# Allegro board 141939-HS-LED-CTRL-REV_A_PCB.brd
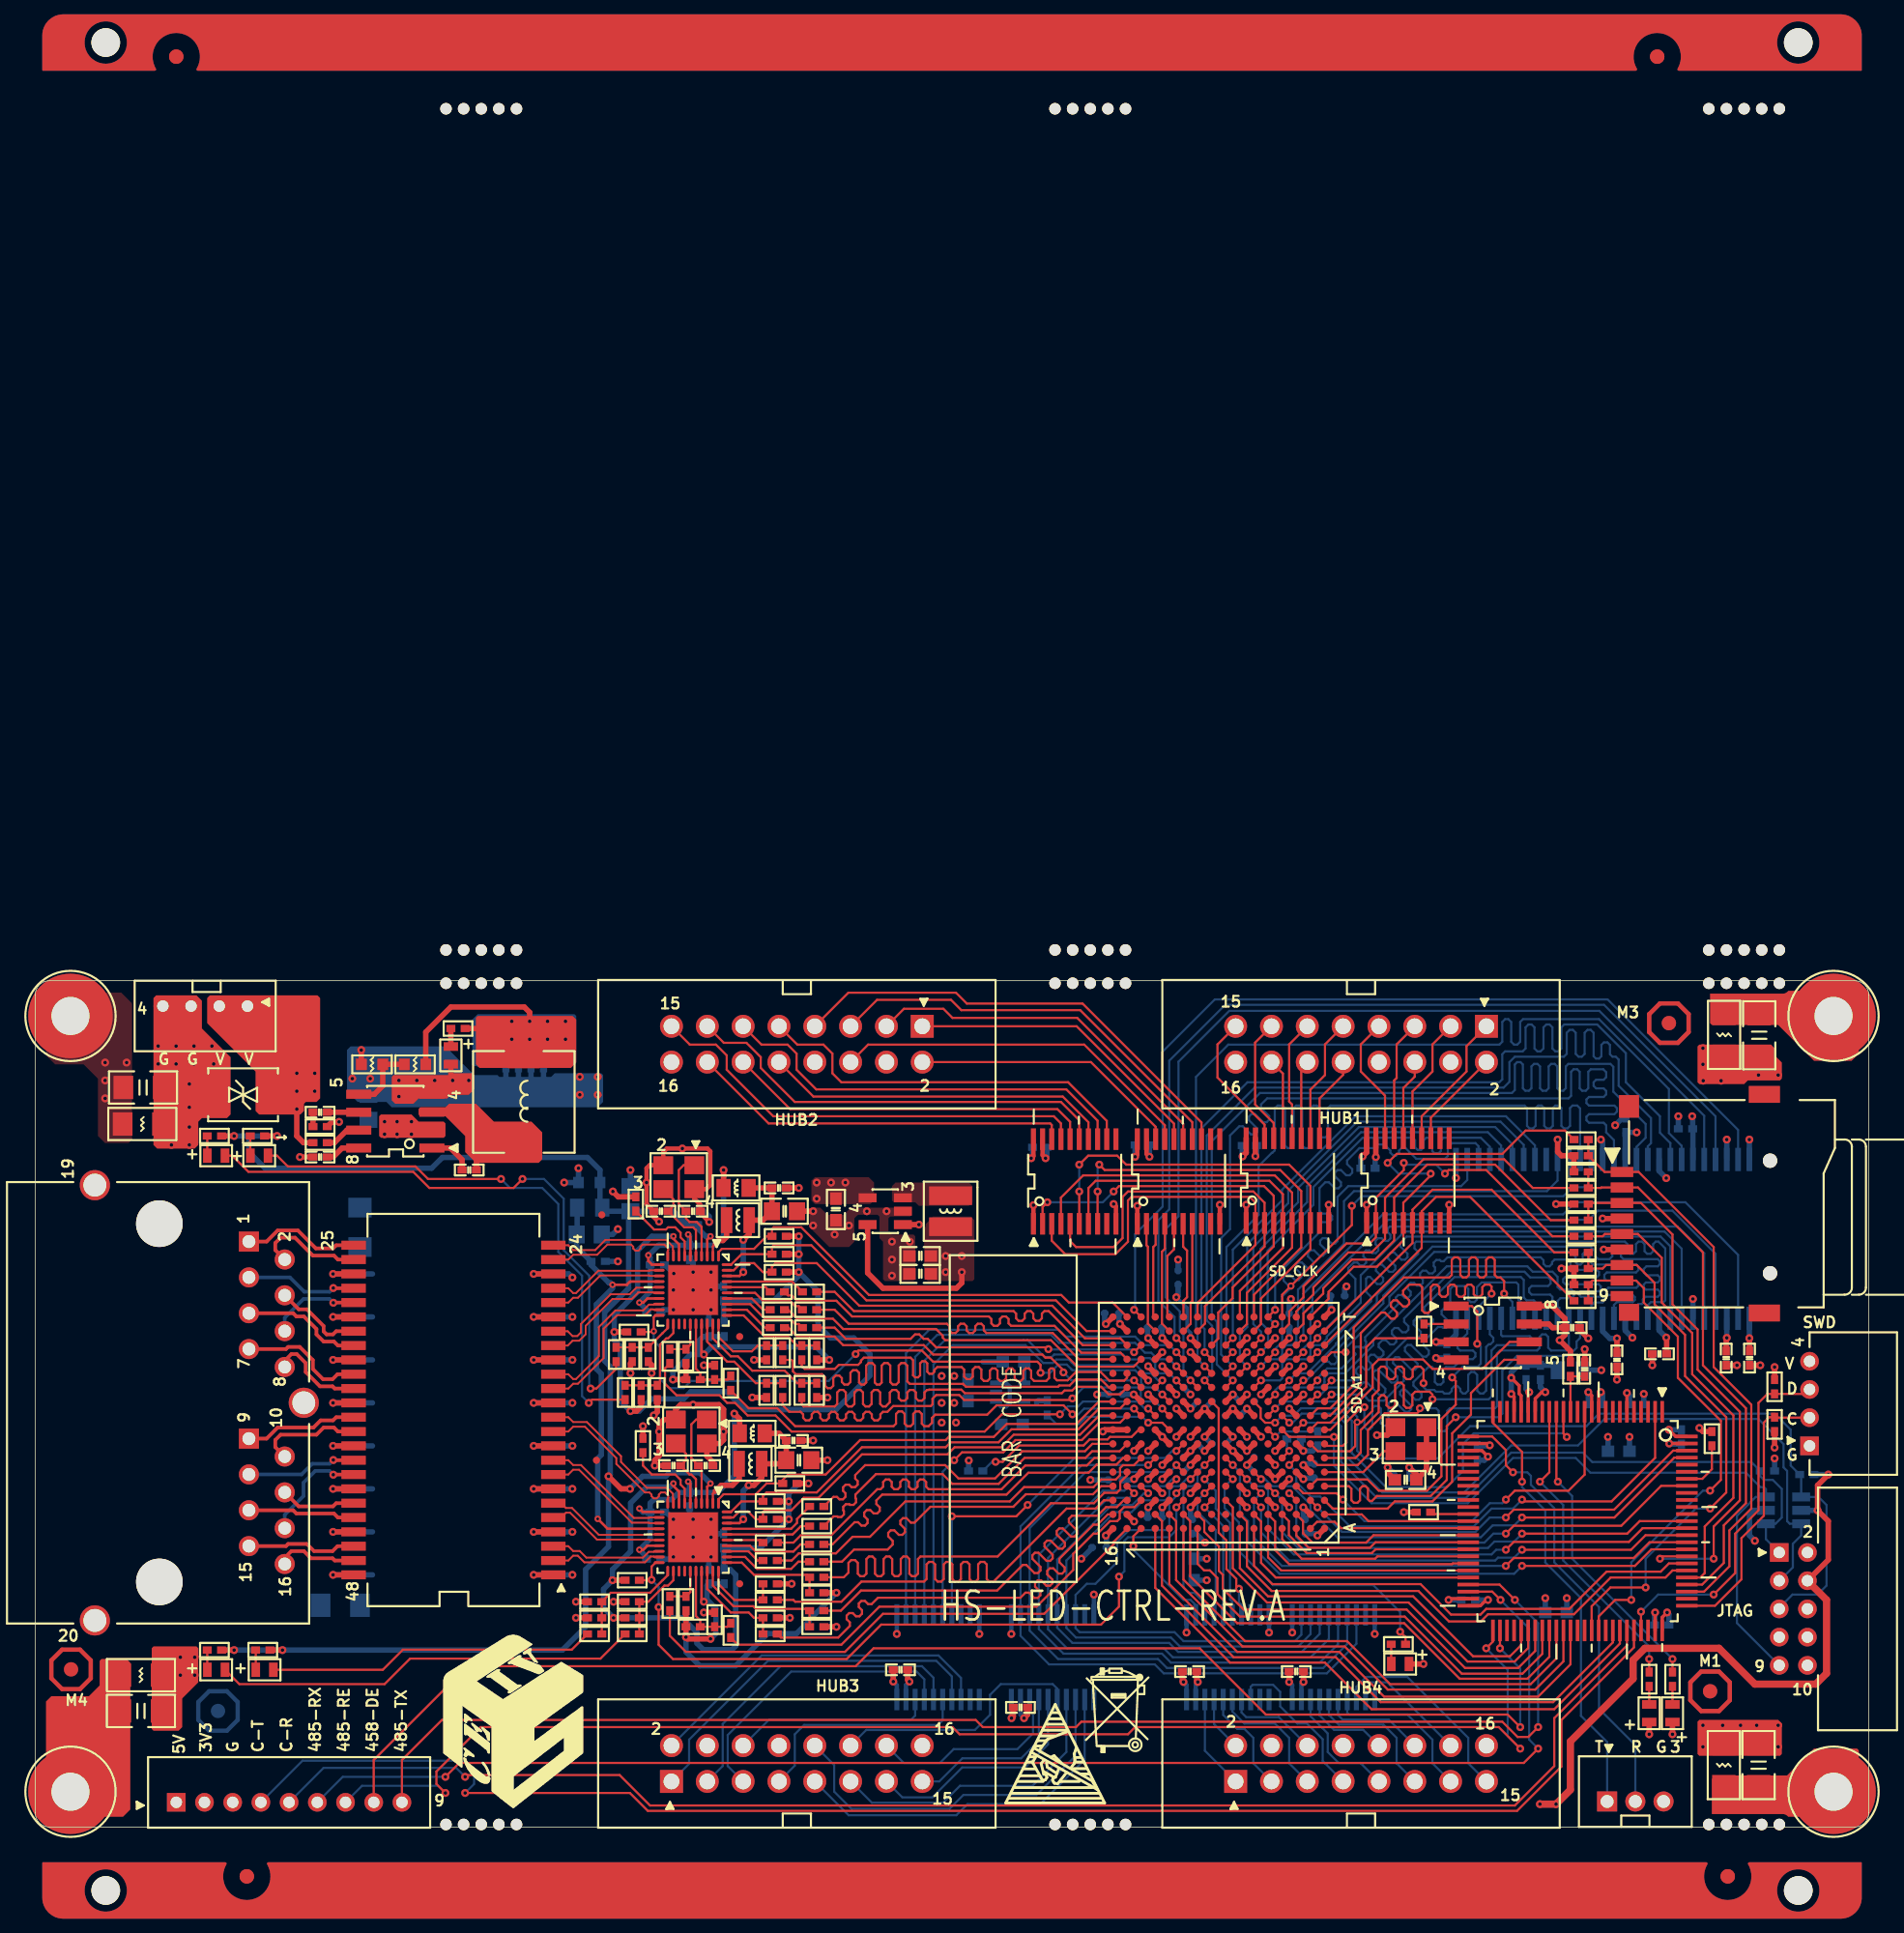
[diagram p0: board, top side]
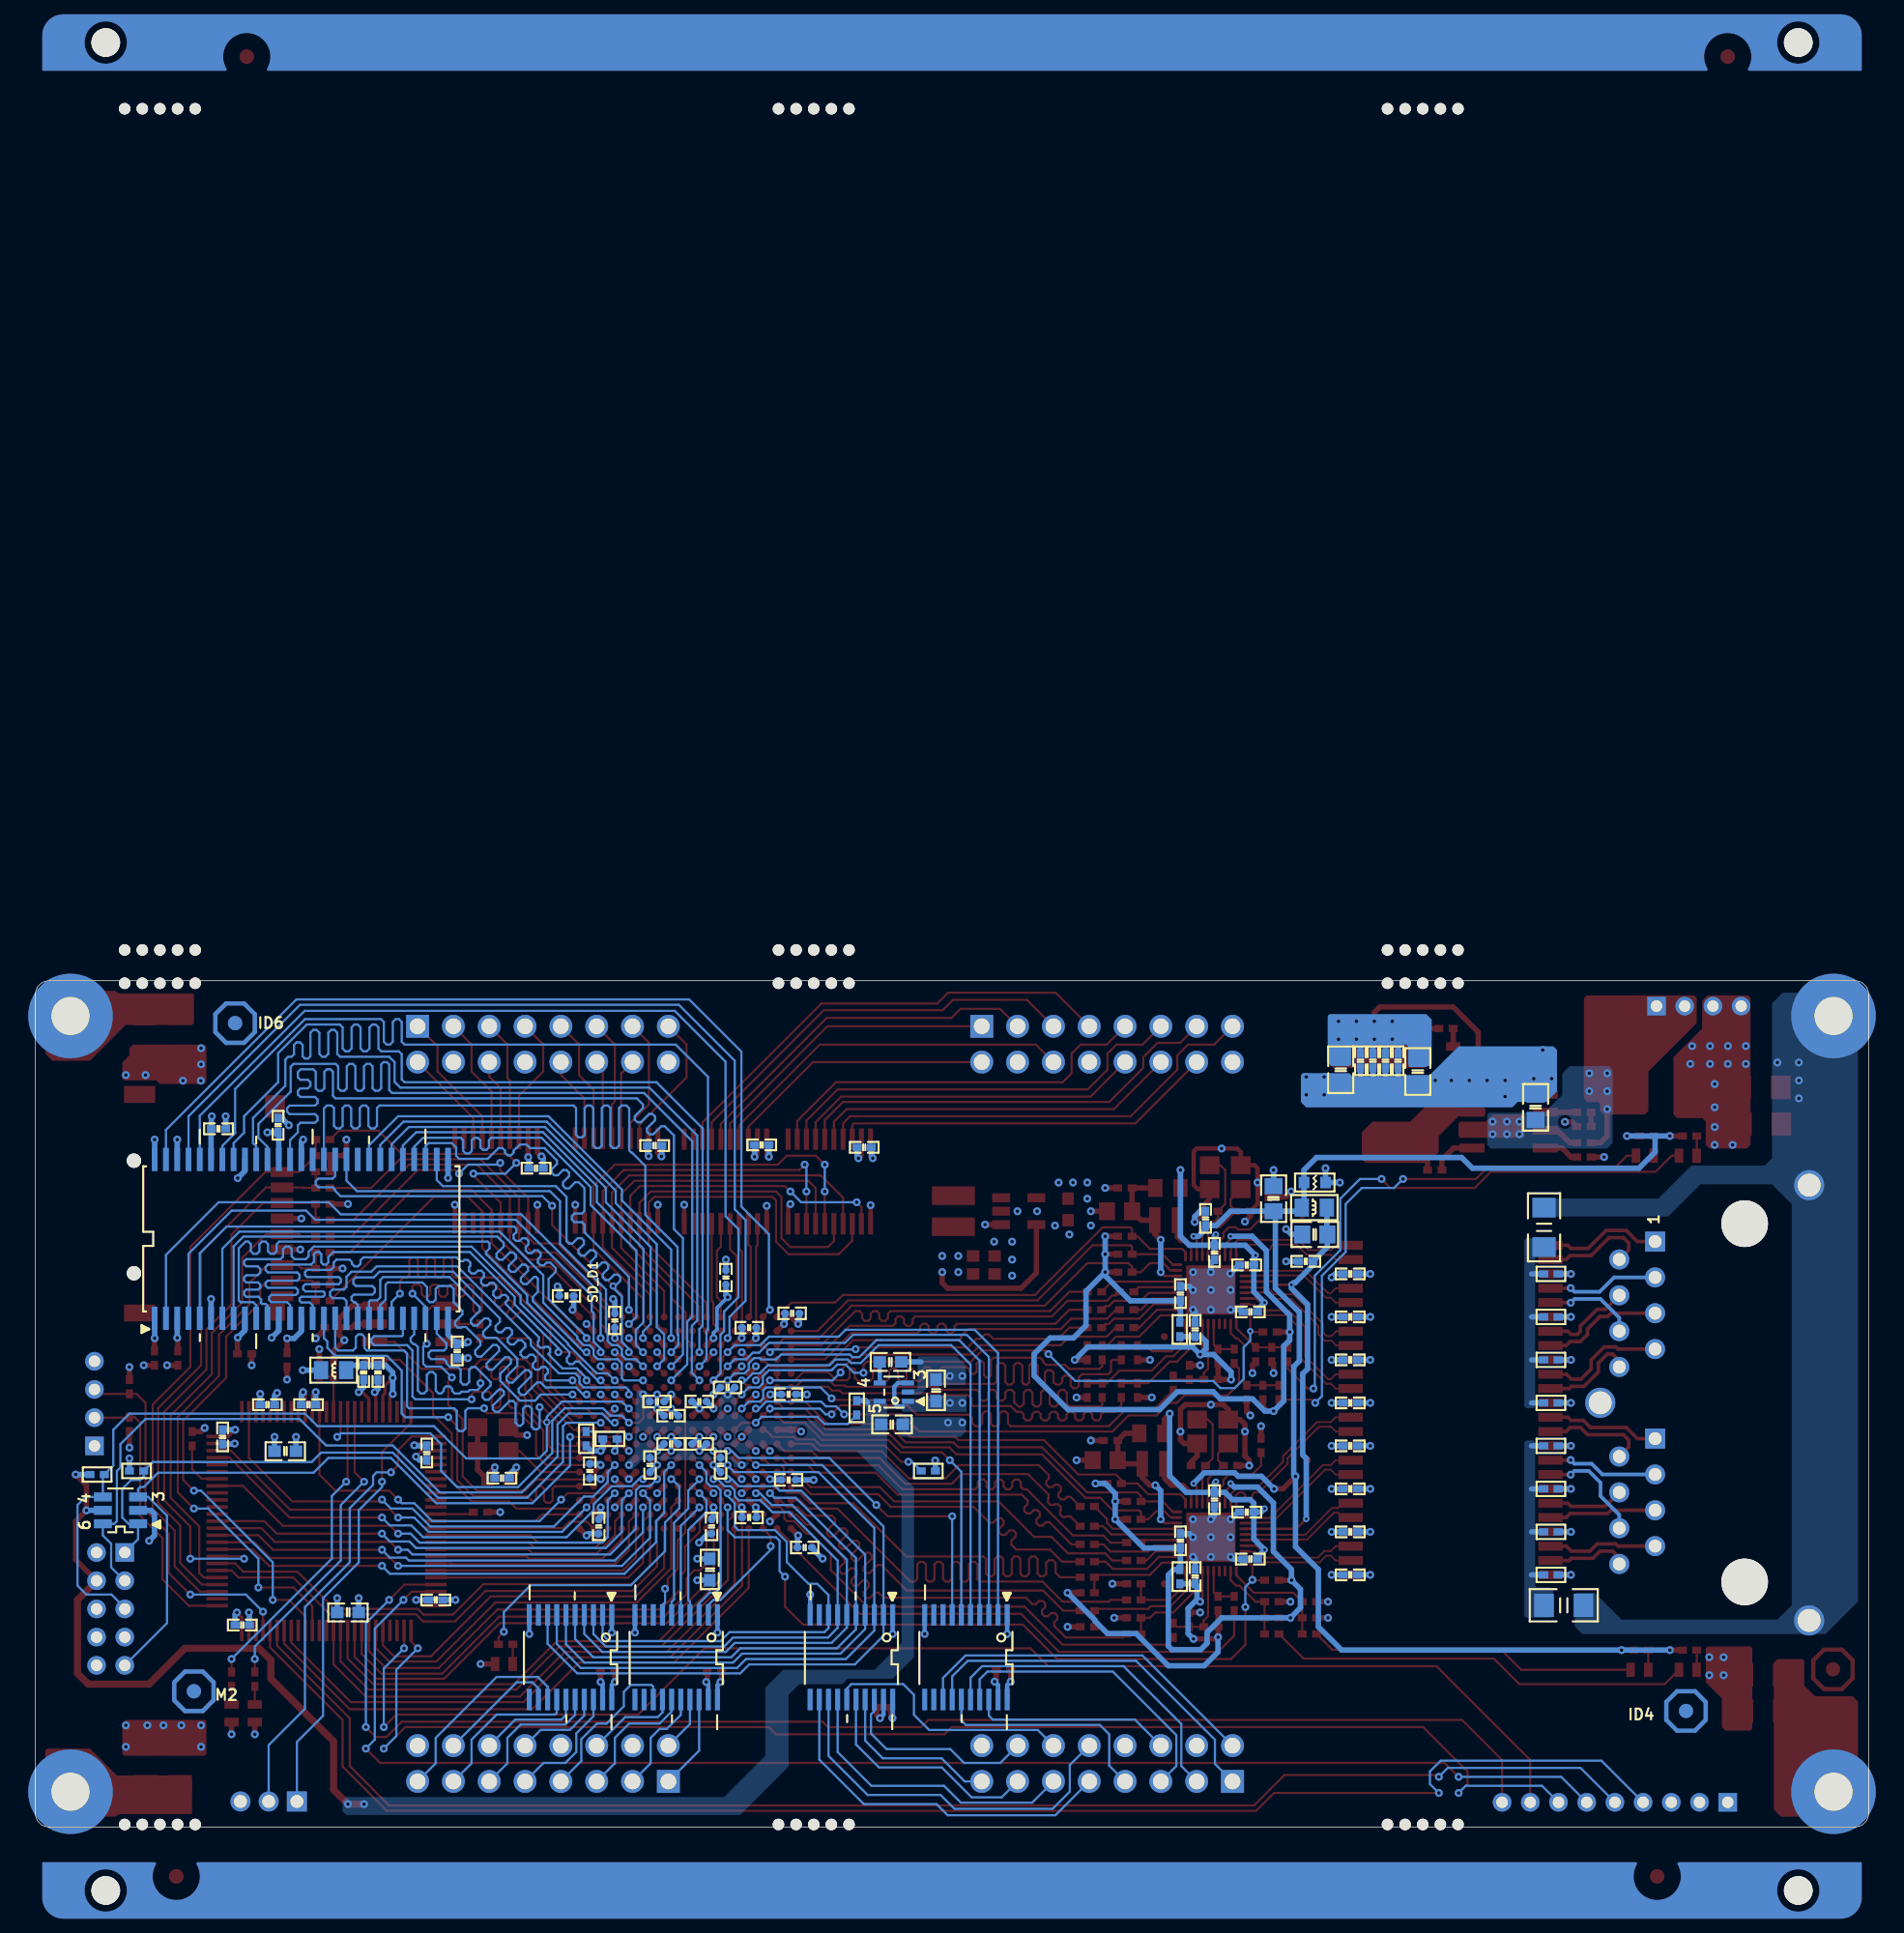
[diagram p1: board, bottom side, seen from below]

Outline 130 x 60 mm; copper layers: TOP, ART02, ART03, BOTTOM. Coordinates in mm from the lower left corner of the outline.
Outline path: 0,59 arc(0.29,59.71) 1,60 129,60 arc(129.71,59.71) 130,59 130,1 arc(129.71,0.29) 129,0 1,0 arc(0.29,0.29) 0,1 0,59

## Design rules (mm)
net group DIFFPAIR0: nets ENETA_MDI_N0 ENETA_MDI_P0
net group DIFFPAIR1: nets ENETA_MDI_N1 ENETA_MDI_P1
net group DIFFPAIR2: nets ENETA_MDI_N2 ENETA_MDI_P2
net group DIFFPAIR3: nets ENETA_MDI_N3 ENETA_MDI_P3
net group DIFFPAIR4: nets ENETB_MDI_N0 ENETB_MDI_P0
net group DIFFPAIR5: nets ENETB_MDI_N1 ENETB_MDI_P1
net group DIFFPAIR6: nets ENETB_MDI_N2 ENETB_MDI_P2
net group DIFFPAIR7: nets ENETB_MDI_N3 ENETB_MDI_P3
net group ENETA_GTX_CLK: nets ENETA_GTX_CLK MIIA_GTX_CLK
net group ENETA_RX_D0: nets ENETA_RX_D0 MIIA_RX_D0
net group ENETA_RX_D1: nets ENETA_RX_D1 MIIA_RX_D1
net group ENETA_RX_DV: nets ENETA_RX_DV MIIA_RX_DV
net group ENETA_TX_D0: nets ENETA_TX_D0 MIIA_TX_D0
net group ENETA_TX_D1: nets ENETA_TX_D1 MIIA_TX_D1
net group ENETA_TX_D2: nets ENETA_TX_D2 MIIA_TX_D2
net group ENETA_TX_D3: nets ENETA_TX_D3 MIIA_TX_D3
net group ENETA_TX_EN: nets ENETA_TX_EN MIIA_TX_EN
net group ENETB_GTX_CLK: nets ENETB_GTX_CLK MIIB_GTX_CLK
net group ENETB_RX_D0: nets ENETB_RX_D0 MIIB_RX_D0
net group ENETB_RX_D1: nets ENETB_RX_D1 MIIB_RX_D1
net group ENETB_RX_DV: nets ENETB_RX_DV MIIB_RX_DV
net group ENETB_TX_D0: nets ENETB_TX_D0 MIIB_TX_D0
net group ENETB_TX_D1: nets ENETB_TX_D1 MIIB_TX_D1
net group ENETB_TX_D2: nets ENETB_TX_D2 MIIB_TX_D2
net group ENETB_TX_D3: nets ENETB_TX_D3 MIIB_TX_D3
net group ENETB_TX_EN: nets ENETB_TX_EN MIIB_TX_EN
net group ENETA_RX_CLK: nets ENETA_RX_CLK ENETA_RX_D2 ENETA_RX_D3 MIIA_RX_CLK MIIA_RX_D2 MIIA_RX_D3 VDDIO_A_RGMII
net group ENETB_RX_CLK: nets ENETB_RX_CLK ENETB_RX_D2 ENETB_RX_D3 MIIB_RX_CLK MIIB_RX_D2 MIIB_RX_D3 VDDIO_B_RGMII
net group POWER: nets ENET_AVDD_3.3 ENET_DVDD_3.3 ENETA_AVDD_1.1 ENETA_DVDD_1.1 ENETA_DVDD_2.5 ENETB_AVDD_1.1 ENETB_DVDD_1.1 ENETB_DVDD_2.5

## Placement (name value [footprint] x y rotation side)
C1  10u  [C0805]  23.63 51.02 90 bottom
C2  0.1u  [C0402]  20.2 47.5 180 top
C3  33n  [C0402]  20.2 50.68 180 top
C4  0.01u  [C0402]  30.77 46.58 180 top
C5  10u  [C0805]  37.44 53.69 270 bottom
C6  10u  [C0805]  31.98 53.56 270 bottom
C7  0.1u  [C0402]  35.15 54.33 270 bottom
C8  0.1u  [C0402]  36.04 54.33 270 bottom
C9  0.1u  [C0402]  34.26 54.33 270 bottom
C10  0.1u  [C0402]  33.37 54.33 270 bottom
C11  10uF  [C0402]  109.86 32.46 270 top
C28  104  [C0402]  108.97 35.4 180 top
C29  104  [C0402]  112.15 33.12 270 top
C30  104  [C0402]  115.16 33.54 180 top
C31  104  [C0402]  100.08 33.75 270 bottom
C32  104  [C0402]  119.89 33.24 270 top
C33  104  [C0402]  112.78 49.75 90 bottom
C34  104  [C0402]  121.54 33.24 270 top
C35  104  [C0402]  117 49.5 180 bottom
C36  22u/6.3V  [C0603]  112.27 26.64 0 bottom
C37  22u/6.3V  [C0603]  107.83 15.21 0 bottom
C38  22u/6.3V  [C0603]  82.17 18.26 90 bottom
C39  27pF  [C0402]  46.65 43.66 180 top
C40  27pF  [C0402]  47.53 25.62 180 top
C41  27pF  [C0402]  44.36 43.66 0 top
C42  27pF  [C0402]  45.25 25.62 0 top
C43  1uF  [C0402]  48.8 37.82 90 bottom
C44  0.1uF  [C0402]  47.76 35.28 90 bottom
C45  1uF  [C0402]  48.8 20.29 90 bottom
C46  0.1uF  [C0402]  47.76 17.75 90 bottom
C47  0.1uF  [C0402]  46.39 40.74 270 bottom
C48  0.1uF  [C0402]  44.11 39.85 0 bottom
C49  10uF  [C0805]  53.12 43.66 0 top
C50  0.1uF  [C0402]  52.74 45.31 0 top
C51  0.1uF  [C0402]  43.85 36.52 0 bottom
C52  10uF  [C0805]  54.14 26 0 top
C53  0.1uF  [C0402]  53.76 27.4 0 top
C54  0.1uF  [C0402]  46.39 23.21 270 bottom
C55  0.1uF  [C0402]  43.85 18.99 0 bottom
C56  0.1uF  [C0402]  44.11 22.32 0 bottom
C57  0.1uF  [C0402]  47.03 43.15 90 bottom
C58  10uF  [C0805]  42.2 44.55 90 bottom
C59  0.1uF  [C0402]  39.91 40.1 0 bottom
C60  1uF  [C0805]  39.28 42.01 0 bottom
C226  0.1uF  [C0402]  36.76 17.88 180 bottom
C227  0.1uF  [C0402]  36.76 20.92 180 bottom
C228  0.1uF  [C0402]  36.76 23.97 180 bottom
C229  0.1uF  [C0402]  36.76 27.02 180 bottom
C230  0.1uF  [C0402]  36.76 30.07 180 bottom
C231  0.1uF  [C0402]  36.76 33.12 180 bottom
C232  0.1uF  [C0402]  36.76 36.16 180 bottom
C233  0.1uF  [C0402]  36.76 39.21 180 bottom
C236  1000pF/2KV  [C1206]  23.02 42.51 270 bottom
C238  22u/6.3V  [C0603]  56.77 43.78 270 top
C239  22u/6.3V  [C0603]  62.74 40.48 180 top
C240  22u/6.3V  [C0603]  62.74 39.21 180 top
C241  22u/6.3V  [C0603]  66.14 30.96 90 bottom
C242  22u/6.3V  [C0603]  69.36 32.97 180 bottom
C243  22u/6.3V  [C0603]  69.25 28.54 180 bottom
C244  0.1uF  [C0402]  101.6 16.1 0 bottom
C245  0.1uF  [C0402]  116.72 27.66 90 bottom
C246  0.1uF  [C0402]  110.62 29.94 180 bottom
C247  0.1uF  [C0402]  115.32 14.32 0 bottom
C248  0.1uF  [C0402]  102.24 26.51 270 bottom
C251  1uF  [C0402]  106.72 32.23 90 bottom
C252  10nF  [C0402]  105.7 32.23 90 bottom
C253  4.7uF  [C0402]  113.54 29.94 180 bottom
C254  104  [SC0402]  75.44 19.81 180 bottom
C255  104  [SC0402]  92.33 37.66 0 bottom
C256  104  [SC0402]  85.92 30.16 180 bottom
C257  104  [SC0402]  86.41 25.67 270 bottom
C258  104  [SC0402]  82.92 27.16 0 bottom
C259  104  [SC0402]  82.92 30.16 0 bottom
C260  104  [SC0402]  84.92 27.16 180 bottom
C261  104  [SC0402]  84.92 29.16 180 bottom
C262  104  [SC0402]  76.33 36.42 0 bottom
C263  104  [SC0402]  88.9 35.91 90 bottom
C264  104  [SC0402]  79.38 21.94 0 bottom
C265  104  [SC0402]  82.05 21.31 270 bottom
C266  104  [SC0402]  81.03 38.96 90 bottom
C267  104  [SC0402]  90.68 25.24 90 bottom
C268  104  [SC0402]  90.05 21.31 90 bottom
C269  104  [SC0402]  76.59 24.61 180 bottom
C270  104  [SC0402]  76.59 30.68 180 bottom
C271  104  [SC0402]  79.38 35.4 0 bottom
C274  2.2uF  [C0603]  97.16 24.61 180 top
C275  0.1uF  [C0402]  96.91 24.73 180 bottom
C276  104  [SC0402]  81.41 25.67 270 bottom
C277  104  [SC0402]  80.92 31.16 0 bottom
C278  NC  [C1206]  7.65 52.43 0 top
C279  NC  [C1206]  7.5 8.22 0 top
C280  NC  [C1206]  122.19 4.39 90 top
C281  NC  [C1206]  122.23 56.13 270 top
C282  0.1u  [C0402]  94.49 46.71 0 bottom
C283  0.1u  [C0402]  86.08 48.31 0 bottom
C284  0.1u  [C0402]  78.49 48.36 0 bottom
C285  0.1u  [C0402]  71.22 48.19 0 bottom
C286  0.1u  [C0402]  61.35 11.15 0 top
C287  0.1u  [C0402]  69.85 8.48 0 top
C288  0.1u  [C0402]  81.84 11.02 0 top
C289  0.1u  [C0402]  89.41 11.02 0 top
C292  1000pF/2KV  [C1206]  21.63 15.72 0 bottom
D1  LED_R  [D0603]  114.43 8.06 90 top
D2  LED_R  [D0603]  116.08 8.06 90 top
D4  SMBJ-5.0CA  [DO-214AA]  14.74 51.91 0 top
D26  LED_R  [D0603]  29.47 54.71 270 top
D34  LED_Y  [D0603]  16.26 11.15 0 top
D35  LED_G  [D0603]  12.83 11.15 0 top
D36  LED_Y  [D0603]  12.83 47.59 0 top
D37  LED_G  [D0603]  15.88 47.59 0 top
D38  LED_B  [D0603]  96.77 11.56 180 top
FB1  600mAFB10ohm  [L0805]  49.69 45.31 180 top
FB2  600mAFB10ohm  [L0805]  50.84 27.91 180 top
FB3  600mAFB10ohm  [L0805]  39.31 43.91 180 bottom
H1  HOLE  [PAD_D3_5]  2.5 57.5 0 top
H2  HOLE  [PAD_D3_5]  2.5 2.5 0 top
H3  HOLE  [PAD_D3_5]  127.5 2.5 0 top
H4  HOLE  [PAD_D3_5]  127.5 57.5 0 top
J1  JTAG-10  [JTAG-10-2_0]  124.65 15.46 270 top
J2  RJ45-1*2  [RJ8-0102SRFZ]  8.8 30.08 270 top
J3  Header 1x4  [PH-4AW-2_0]  125.8 30.02 90 top
J4  TF_Card  [SD-MICRO]  123 44.19 90 top
J6  CAN&RS485  [PH-9A-2_0]  18 2.45 0 top
J7  CON3  [PH-3A-2_0]  113.45 2.51 0 top
J8  HUB75  [HD2X8-2_54-W]  94 55.5 0 top
J11  HUB75  [HD2X8-2_54-W]  54 55.5 0 top
J12  HUB75  [HD2X8-2_54-W]  94 4.5 180 top
J13  HUB75  [HD2X8-2_54-W]  54 4.5 180 top
J15  DC-5V  [PH-4A-2_0]  12.05 57.5 180 top
L1  10uH  [L7X7]  34.64 51.4 90 top
L6  MIPF2016D4R7  [L2016]  49.82 43.02 180 top
L7  MIPF2016D4R7  [L2016]  50.71 25.75 180 top
L8  4.7uH  [NR3015]  64.9 43.66 270 top
L10  100uH  [L0805]  108.84 32.39 0 bottom
M1  MARK  [TPAD]  118.75 9.62 0 top
M2  MARK  [TPAD]  118.75 9.62 180 bottom
M3  MARK  [TPAD]  115.83 56.99 0 top
M4  MARK  [TPAD]  2.54 11.18 0 top
NOREF  -  []  351.15 39.37 0 top
NOREF#2  -  []  0 0 0 top
NOREF#3  -  [unnamed#2]  121.16 -1 0 top
NOREF#4  -  [unnamed#2]  31.62 -1 0 top
NOREF#5  -  [unnamed#3]  31.62 61 0 top
NOREF#6  -  []  79.25 8.38 0 top
NOREF#7  -  []  0 0 0 top
NOREF#8  -  []  71.63 4.7 0 top
NOREF#9  -  []  -118.75 -80.01 0 top
NOREF#10  -  [unnamed#4]  0 124.01 180 top
NOREF#11  -  []  1 122 0 top
NOREF#12  -  []  0 0 0 top
NOREF#13  -  []  0 124.01 0 top
NOREF#14  -  []  319.66 104.36 0 top
NOREF#15  -  []  0 0 0 top
NOREF#16  -  [unnamed#2]  74.8 123 180 top
NOREF#17  -  []  318.77 148.59 0 top
NOREF#18  -  [unnamed#3]  74.8 61 0 top
NOREF#19  -  []  2.5 2.5 0 top
NOREF#20  -  [unnamed#5]  0 -2 180 top
NOREF#21  -  [unnamed#3]  121.16 61 0 top
NOREF#22  -  []  130 1 0 top
NOREF#23  -  []  1 60 0 top
NOREF#24  -  [unnamed#5]  130 124.01 0 top
NOREF#25  -  []  327.02 196.85 0 top
NOREF#26  -  []  0 -2 0 top
NOREF#27  -  []  2 129.01 0 top
NOREF#28  -  [unnamed#2]  121.16 123 180 top
NOREF#29  -  []  2.5 2.5 0 top
NOREF#30  -  [unnamed#2]  74.8 -1 0 top
NOREF#31  -  []  1 62 0 top
NOREF#32  -  [unnamed#6]  130 -2 180 top
NOREF#33  -  [unnamed#2]  31.62 123 180 top
NOREF#34  -  []  69.34 34.04 90 top
NOREF#35  -  [unnamed#7]  115.83 56.99 180 bottom
NOREF#36  -  [unnamed#7]  12.96 8.22 180 bottom
P1  EP4CE15F256  [FBGA-256]  83.91 28.66 90 top
R1  47k  [R0402]  20.2 48.52 180 top
R2  2.2k  [R0402]  20.2 49.66 0 top
R3  10k/1%  [R0603]  23.88 54.07 0 top
R4  26k/%1  [R0603]  26.93 54.07 180 top
R5  10K  [R0402]  108.84 32.46 270 top
R11  1k  [R0402]  122.81 25.24 180 bottom
R12  10k  [R0402]  125.61 24.99 0 bottom
R13  22R  [R0402]  98.47 35.16 90 top
R16  1k  [R0402]  89.25 27.51 0 bottom
R17  1k  [R0402]  90.94 27.53 270 bottom
R18  1k  [R0402]  66.68 25.24 180 bottom
R22  22R  [R0402]  55.41 17.71 180 top
R23  1.5K  [R0402]  52.11 21.81 180 top
R24  22R  [R0402]  53 33.62 90 top
R25  22R  [R0402]  52.11 16.1 180 top
R26  4.7K  [R0402]  52.11 23.08 180 top
R27  22R  [R0402]  54.35 30.96 90 top
R28  22R  [R0402]  55.41 15.34 180 top
R29  10K  [R0402]  42.33 17.5 0 top
R30  22R  [R0402]  53 30.96 90 top
R31  2.37K  [R0402]  42.58 44.17 90 top
R32  22R  [R0402]  52.11 13.69 180 top
R33  2.37K  [R0402]  43.09 27.05 90 top
R34  4.7K  [R0402]  53.5 24.35 180 top
R35  22R  [R0402]  49.31 31.47 90 top
R36  22R  [R0402]  49.31 13.94 90 top
R37  22R  [R0402]  44.99 33.37 90 top
R38  22R  [R0402]  44.99 15.84 90 top
R39  22R  [R0402]  54.9 35.4 180 top
R40  22R  [R0402]  52.11 18.89 180 top
R41  22R  [R0402]  52.61 35.4 180 top
R42  22R  [R0402]  55.41 18.81 180 top
R43  22R  [R0402]  52.61 36.67 180 top
R44  22R  [R0402]  55.41 20.04 180 top
R45  22R  [R0402]  54.9 36.67 180 top
R46  22R  [R0402]  52.11 20.16 180 top
R47  22R  [R0402]  52.61 37.94 180 top
R48  22R  [R0402]  55.41 21.33 180 top
R49  22R  [R0402]  54.9 37.94 180 top
R50  22R  [R0402]  55.41 22.73 180 top
R51  1K  [R0402]  41.18 33.5 270 top
R52  1K  [R0402]  39.66 13.69 180 top
R56  1K  [R0402]  41.82 30.81 270 top
R60  1K  [R0402]  42.33 13.69 180 top
R73  10k  [R0402]  43.47 33.5 90 top
R76  10k  [R0402]  44.11 30.81 90 top
R77  10k  [R0402]  39.66 15.97 0 top
R89  10k  [R0402]  42.33 15.97 0 top
R90  10K  [R0402]  42.33 33.5 90 top
R91  10K  [R0402]  55.41 33.62 90 top
R92  10K  [R0402]  39.66 14.83 0 top
R93  10K  [R0402]  55.41 16.61 180 top
R94  0R  [R0603]  39.28 45.69 0 bottom
R95  10K  [R0402]  55.41 30.96 90 top
R96  10K  [R0402]  46.14 33.37 90 top
R97  10K  [R0402]  55.41 14.19 180 top
R98  10K  [R0402]  46.14 15.84 90 top
R99  10K  [R0402]  51.85 30.96 90 top
R100  10K  [R0402]  42.96 30.81 90 top
R101  10K  [R0402]  52.11 14.83 180 top
R102  10K  [R0402]  42.33 14.83 0 top
R103  DNI  [R0402]  46.65 31.72 0 top
R104  DNI  [R0402]  46.65 14.19 0 top
R105  10K  [R0402]  48.17 32.23 270 top
R106  10K  [R0402]  48.17 14.7 270 top
R107  10K  [R0402]  51.85 33.62 90 top
R108  10K  [R0402]  52.11 17.24 180 top
R111  75R  [R0402]  22.54 17.88 0 bottom
R112  75R  [R0402]  22.54 20.92 0 bottom
R113  75R  [R0402]  22.54 23.97 0 bottom
R114  75R  [R0402]  22.54 27.02 0 bottom
R115  75R  [R0402]  22.54 30.07 0 bottom
R116  75R  [R0402]  22.54 33.12 0 bottom
R117  75R  [R0402]  22.54 36.16 0 bottom
R118  75R  [R0402]  22.54 39.21 0 bottom
R120  0  [R0402]  48.85 35.28 90 bottom
R121  22R  [R0402]  54.35 33.62 90 top
R122  0  [R0402]  48.85 17.75 90 bottom
R123  1.5K  [R0402]  52.74 39.34 180 top
R124  4.7K  [R0402]  52.74 40.61 180 top
R125  10K  [R0402]  42.45 35.1 0 top
R126  4.7K  [R0402]  52.74 41.88 180 top
R127  4.7K  [R0402]  116.08 10.48 90 top
R128  4.7K  [R0402]  114.43 10.48 90 top
R129  10K  [R0402]  123.32 28.54 90 top
R130  10K  [R0402]  123.32 31.21 90 top
R131  10K  [R0402]  118.88 27.53 270 top
R135  10K  [R0402]  98.43 22.32 0 top
R137  10K  [R0402]  109.61 38.45 0 top
R138  10K  [R0402]  109.61 39.59 0 top
R139  10K  [R0402]  109.61 44.17 0 top
R140  10K  [R0402]  109.61 46.45 0 top
R141  10K  [R0402]  109.61 47.59 0 top
R142  2.2K  [R0402]  29.98 56.61 0 top
R146  1k  [R0402]  15.75 48.99 180 top
R147  1k  [R0402]  12.7 48.99 180 top
R148  1k  [R0402]  12.7 12.54 180 top
R149  1k  [R0402]  16.13 12.54 180 top
R154  NC  [R1206]  7.59 49.84 0 top
R155  NC  [R1206]  7.5 10.76 0 top
R156  NC  [R1206]  119.72 4.39 90 top
R157  NC  [R1206]  119.74 56.16 270 top
R158  0  [R0402]  109.61 40.74 0 top
R159  0  [R0402]  109.61 37.31 0 top
R160  0  [R0402]  109.61 48.74 0 top
R161  0  [R0402]  109.61 45.31 0 top
R162  0  [R0402]  109.61 43.02 0 top
R163  0  [R0402]  109.61 41.88 0 top
R164  0  [R0402]  71.75 29.72 90 bottom
R165  1k  [R0402]  96.65 12.95 180 top
U1  MP1482DS  [SOIC8]  25.53 50.04 90 top
U5  HY57V641620HT-H  [TSOP-II-54]  111.13 41.7 180 bottom
U6  SRV05-4  [SOT23-6]  123.96 22.45 90 bottom
U7  EPCS16  [SO8]  103.34 35.03 270 top
U8  AR8035  [QFN40#2]  46.65 38.07 180 top
U9  AR8035  [QFN40]  46.65 20.54 180 top
U23  H5014NL  [TFM48-40-480]  29.65 29.56 90 top
U24  RT8008-12GJ5  [TSOT-23-5]  60.27 43.66 90 top
U25  RT9193-25GU5  [SC-70-5]  69.13 30.83 90 bottom
U26  STM32F103VET6  [QFP100-20-1414]  109.35 21.69 180 top
U27  TC74VHC245  [TSSOP-20]  97.32 45.83 0 top
U28  TC74VHC245  [TSSOP-20]  88.78 45.83 0 top
U29  TC74VHC245  [TSSOP-20]  73.7 45.77 0 top
U30  TC74VHC245  [TSSOP-20]  81.06 45.77 0 top
U31  TC74VHC245  [TSSOP-20]  72.13 12.03 0 bottom
U32  TC74VHC245  [TSSOP-20]  64.01 12.03 0 bottom
U33  TC74VHC245  [TSSOP-20]  92.05 12.03 0 bottom
U34  TC74VHC245  [TSSOP-20]  84.55 12.03 0 bottom
X4  OXJTDLJANF-25M  [3_2X2_5_4P]  97.54 27.5 180 top
Y1  XXCBPLNANF-25M  [3_2X2_5_4P]  45.63 46.07 180 top
Y2  XXCBPLNANF-25M  [3_2X2_5_4P]  46.52 28.04 180 top

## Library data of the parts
C1 C5 C6 = C0805
C2 C7-C10 C282-C289 = C0402
C3 C4 C11 C28-C35 C39-C48 C50 C51 C53-C57 C59 C226-C233 C244-C248 C251-C253 C275 = C0402: tolerance: 0.1u
C36-C38 C238-C243 = C0603
C49 C52 C58 C60 = C0805: tolerance: 10u
C236 C292 = C1206
C254-C271 C276 C277 = SC0402
C274 = C0603: tolerance: 22u/6.3V
C278-C281 = C1206: tolerance: 1000pF/2KV
D1 D2 D26 = D0603
D4 = DO-214AA
D34-D38 = D0603: tolerance: LED_R
FB1-FB3 = L0805
H1-H4 = PAD_D3_5
J1 = JTAG-10-2_0
J2 = RJ8-0102SRFZ
J3 = PH-4AW-2_0
J4 = SD-MICRO
J6 = PH-9A-2_0
J7 = PH-3A-2_0
J8 J11-J13 = HD2X8-2_54-W
J15 = PH-4A-2_0
L1 = L7X7
L6 L7 = L2016
L8 = NR3015
L10 = L0805: tolerance: 600mAFB10ohm
M1-M4 = TPAD
P1 = FBGA-256
R1 R2 R11 R13 R16-R18 R23 R26 R31 R33 R34 R51 R52 R56 R60 R111-R118 R120 R122-R124 R126-R128 R142 R146-R149 R158-R165 = R0402: tolerance: 10k
R3 = R0603
R4 R94 = R0603: tolerance: 10k/1%
R5 R29 R90-R93 R95-R102 R105-R108 R125 R129-R131 R135 R137-R141 = R0402: tolerance: 10k; signal model: R0402_10K
R12 R73 R76 R77 R89 = R0402
R22 R24 R25 R27 R28 R30 R32 R35-R50 R121 = R0402: tolerance: 10k; signal model: R0402_22R
R103 R104 = R0402: tolerance: 10k; signal model: R0402_DNI
R154-R157 = R1206: tolerance: 0
U1 = SOIC8
U5 = TSOP-II-54
U6 = SOT23-6
U7 = SO8
U8 U9 = QFN40
U23 = TFM48-40-480
U24 = TSOT-23-5: tolerance: RT8008X_5P
U25 = SC-70-5: tolerance: RT9193
U26 = QFP100-20-1414: tolerance: STM32F103VE
U27-U34 = TSSOP-20: tolerance: 74VHC245
X4 = 3_2X2_5_4P
Y1 Y2 = 3_2X2_5_4P: tolerance: OXJTDLJANF-25M

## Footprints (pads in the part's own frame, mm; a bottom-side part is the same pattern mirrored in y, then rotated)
3_2X2_5_4P
  rect 1.397x1.27 smd: 1(-1.1,-0.85) 2(1.1,-0.85) 3(1.1,0.85) 4(-1.1,0.85)
C0402
  rect 0.635x0.508 smd: 1(-0.508,0) 2(0.508,0)
C0603
  rect 0.889x0.813 smd: 1(-0.762,0) 2(0.762,0)
C0805
  rect 1.143x1.27 smd: 1(-0.889,0) 2(0.889,0)
C1206
  rect 1.397x1.651 smd: 1(-1.397,0) 2(1.397,0)
D0603
  rect 0.61x1.016 smd: 1(-0.625,0) 2(0.625,0)
DO-214AA
  rect 1.626x2.337 smd: 1(-2.2,0) 2(2.2,0)
FBGA-256
  round 0.508 smd: A1(-7.5,-7.5) A2(-7.5,-6.5) A3(-7.5,-5.5) A4(-7.5,-4.5) A5(-7.5,-3.5) A6(-7.5,-2.5) A7(-7.5,-1.5) A8(-7.5,-0.5) A9(-7.5,0.5) A10(-7.5,1.5) A11(-7.5,2.5) A12(-7.5,3.5) A13(-7.5,4.5) A14(-7.5,5.5) A15(-7.5,6.5) A16(-7.5,7.5) B1(-6.5,-7.5) B2(-6.5,-6.5) B3(-6.5,-5.5) B4(-6.5,-4.5) B5(-6.5,-3.5) B6(-6.5,-2.5) B7(-6.5,-1.5) B8(-6.5,-0.5) B9(-6.5,0.5) B10(-6.5,1.5) B11(-6.5,2.5) B12(-6.5,3.5) B13(-6.5,4.5) B14(-6.5,5.5) B15(-6.5,6.5) B16(-6.5,7.5) C1(-5.5,-7.5) C2(-5.5,-6.5) C3(-5.5,-5.5) C4(-5.5,-4.5) C5(-5.5,-3.5) C6(-5.5,-2.5) C7(-5.5,-1.5) C8(-5.5,-0.5) C9(-5.5,0.5) C10(-5.5,1.5) C11(-5.5,2.5) C12(-5.5,3.5) C13(-5.5,4.5) C14(-5.5,5.5) C15(-5.5,6.5) C16(-5.5,7.5) D1(-4.5,-7.5) D2(-4.5,-6.5) D3(-4.5,-5.5) D4(-4.5,-4.5) D5(-4.5,-3.5) D6(-4.5,-2.5) D7(-4.5,-1.5) D8(-4.5,-0.5) D9(-4.5,0.5) D10(-4.5,1.5) D11(-4.5,2.5) D12(-4.5,3.5) D13(-4.5,4.5) D14(-4.5,5.5) D15(-4.5,6.5) D16(-4.5,7.5) E1(-3.5,-7.5) E2(-3.5,-6.5) E3(-3.5,-5.5) E4(-3.5,-4.5) E5(-3.5,-3.5) E6(-3.5,-2.5) E7(-3.5,-1.5) E8(-3.5,-0.5) E9(-3.5,0.5) E10(-3.5,1.5) E11(-3.5,2.5) E12(-3.5,3.5) E13(-3.5,4.5) E14(-3.5,5.5) E15(-3.5,6.5) E16(-3.5,7.5) F1(-2.5,-7.5) F2(-2.5,-6.5) F3(-2.5,-5.5) F4(-2.5,-4.5) F5(-2.5,-3.5) F6(-2.5,-2.5) F7(-2.5,-1.5) F8(-2.5,-0.5) F9(-2.5,0.5) F10(-2.5,1.5) F11(-2.5,2.5) F12(-2.5,3.5) F13(-2.5,4.5) F14(-2.5,5.5) F15(-2.5,6.5) F16(-2.5,7.5) G1(-1.5,-7.5) G2(-1.5,-6.5) G3(-1.5,-5.5) G4(-1.5,-4.5) G5(-1.5,-3.5) G6(-1.5,-2.5) G7(-1.5,-1.5) G8(-1.5,-0.5) G9(-1.5,0.5) G10(-1.5,1.5) G11(-1.5,2.5) G12(-1.5,3.5) G13(-1.5,4.5) G14(-1.5,5.5) G15(-1.5,6.5) G16(-1.5,7.5) H1(-0.5,-7.5) H2(-0.5,-6.5) H3(-0.5,-5.5) H4(-0.5,-4.5) H5(-0.5,-3.5) H6(-0.5,-2.5) H7(-0.5,-1.5) H8(-0.5,-0.5) H9(-0.5,0.5) H10(-0.5,1.5) H11(-0.5,2.5) H12(-0.5,3.5) H13(-0.5,4.5) H14(-0.5,5.5) H15(-0.5,6.5) H16(-0.5,7.5) J1(0.5,-7.5) J2(0.5,-6.5) J3(0.5,-5.5) J4(0.5,-4.5) J5(0.5,-3.5) J6(0.5,-2.5) J7(0.5,-1.5) J8(0.5,-0.5) J9(0.5,0.5) J10(0.5,1.5) J11(0.5,2.5) J12(0.5,3.5) J13(0.5,4.5) J14(0.5,5.5) J15(0.5,6.5) J16(0.5,7.5) K1(1.5,-7.5) K2(1.5,-6.5) K3(1.5,-5.5) K4(1.5,-4.5) K5(1.5,-3.5) K6(1.5,-2.5) K7(1.5,-1.5) K8(1.5,-0.5) K9(1.5,0.5) K10(1.5,1.5) K11(1.5,2.5) K12(1.5,3.5) K13(1.5,4.5) K14(1.5,5.5) K15(1.5,6.5) K16(1.5,7.5) L1(2.5,-7.5) L2(2.5,-6.5) L3(2.5,-5.5) L4(2.5,-4.5) L5(2.5,-3.5) L6(2.5,-2.5) L7(2.5,-1.5) L8(2.5,-0.5) L9(2.5,0.5) L10(2.5,1.5) L11(2.5,2.5) L12(2.5,3.5) L13(2.5,4.5) L14(2.5,5.5) L15(2.5,6.5) L16(2.5,7.5) M1(3.5,-7.5) M2(3.5,-6.5) M3(3.5,-5.5) M4(3.5,-4.5) M5(3.5,-3.5) M6(3.5,-2.5) M7(3.5,-1.5) M8(3.5,-0.5) M9(3.5,0.5) M10(3.5,1.5) M11(3.5,2.5) M12(3.5,3.5) M13(3.5,4.5) M14(3.5,5.5) M15(3.5,6.5) M16(3.5,7.5) N1(4.5,-7.5) N2(4.5,-6.5) N3(4.5,-5.5) N4(4.5,-4.5) N5(4.5,-3.5) N6(4.5,-2.5) N7(4.5,-1.5) N8(4.5,-0.5) N9(4.5,0.5) N10(4.5,1.5) N11(4.5,2.5) N12(4.5,3.5) N13(4.5,4.5) N14(4.5,5.5) N15(4.5,6.5) N16(4.5,7.5) P1(5.5,-7.5) P2(5.5,-6.5) P3(5.5,-5.5) P4(5.5,-4.5) P5(5.5,-3.5) P6(5.5,-2.5) P7(5.5,-1.5) P8(5.5,-0.5) P9(5.5,0.5) P10(5.5,1.5) P11(5.5,2.5) P12(5.5,3.5) P13(5.5,4.5) P14(5.5,5.5) P15(5.5,6.5) P16(5.5,7.5) R1(6.5,-7.5) R2(6.5,-6.5) R3(6.5,-5.5) R4(6.5,-4.5) R5(6.5,-3.5) R6(6.5,-2.5) R7(6.5,-1.5) R8(6.5,-0.5) R9(6.5,0.5) R10(6.5,1.5) R11(6.5,2.5) R12(6.5,3.5) R13(6.5,4.5) R14(6.5,5.5) R15(6.5,6.5) R16(6.5,7.5) T1(7.5,-7.5) T2(7.5,-6.5) T3(7.5,-5.5) T4(7.5,-4.5) T5(7.5,-3.5) T6(7.5,-2.5) T7(7.5,-1.5) T8(7.5,-0.5) T9(7.5,0.5) T10(7.5,1.5) T11(7.5,2.5) T12(7.5,3.5) T13(7.5,4.5) T14(7.5,5.5) T15(7.5,6.5) T16(7.5,7.5)
HD2X8-2_54-W
  rect 1.626x1.626 hole 1.118: 1(8.89,1.27)
  round 1.626 hole 1.118: 2(8.89,-1.27) 3(6.35,1.27) 4(6.35,-1.27) 5(3.81,1.27) 6(3.81,-1.27) 7(1.27,1.27) 8(1.27,-1.27) 9(-1.27,1.27) 10(-1.27,-1.27) 11(-3.81,1.27) 12(-3.81,-1.27) 13(-6.35,1.27) 14(-6.35,-1.27) 15(-8.89,1.27) 16(-8.89,-1.27)
JTAG-10-2_0
  rect 1.321x1.321 hole 0.813: 1(-4,-1)
  round 1.321 hole 0.813: 2(-4,1) 3(-2,-1) 4(-2,1) 5(0,-1) 6(0,1) 7(2,-1) 8(2,1) 9(4,-1) 10(4,1)
L7X7
  rect 1.524x2.235 smd: 1(-3.15,0) 2(3.15,0)
L0805
  rect 1.016x1.27 smd: 1(-0.889,0) 2(0.889,0)
L2016
  rect 0.813x1.829 smd: 1(-0.8,0) 2(0.8,0)
NR3015
  rect 1.321x3.048 smd: 1(-1.1,0) 2(1.1,0)
PAD_D3_5
  round 5.994 hole 2.692: 1(0,0)
PH-3A-2_0
  rect 1.422x1.422 hole 0.914: 1(-2,-0.7)
  round 1.422 hole 0.914: 2(0,-0.7) 3(2,-0.7)
PH-4A-2_0
  rect 1.321x1.321 hole 0.813: 1(-3,-0.7)
  round 1.321 hole 0.813: 2(-1,-0.7) 3(1,-0.7) 4(3,-0.7)
PH-4AW-2_0
  rect 1.321x1.321 hole 0.813: 1(-3,0)
  round 1.321 hole 0.813: 2(-1,0) 3(1,0) 4(3,0)
PH-9A-2_0
  rect 1.321x1.321 hole 0.813: 1(-8,-0.7)
  round 1.321 hole 0.813: 2(-6,-0.7) 3(-4,-0.7) 4(-2,-0.7) 5(0,-0.7) 6(2,-0.7) 7(4,-0.7) 8(6,-0.7) 9(8,-0.7)
QFN40
  round 0.5 smd: (-3.3,3.3) (6.856,-5.459)
  oval 0.203x0.762 smd: 1(-1.8,-2.405) 2(-1.4,-2.405) 3(-1,-2.405) 4(-0.6,-2.405) 5(-0.2,-2.405) 6(0.2,-2.405) 7(0.6,-2.405) 8(1,-2.405) 9(1.4,-2.405) 10(1.8,-2.405) 21(1.8,2.405) 22(1.4,2.405) 23(1,2.405) 24(0.6,2.405) 25(0.2,2.405) 26(-0.2,2.405) 27(-0.6,2.405) 28(-1,2.405) 29(-1.4,2.405) 30(-1.8,2.405)
  oval 0.762x0.203 smd: 11(2.405,-1.8) 12(2.405,-1.4) 13(2.405,-1) 14(2.405,-0.6) 15(2.405,-0.2) 16(2.405,0.2) 17(2.405,0.6) 18(2.405,1) 19(2.405,1.4) 20(2.405,1.8) 31(-2.405,1.8) 32(-2.405,1.4) 33(-2.405,1) 34(-2.405,0.6) 35(-2.405,0.2) 36(-2.405,-0.2) 37(-2.405,-0.6) 38(-2.405,-1) 39(-2.405,-1.4) 40(-2.405,-1.8)
  rect 3.505x3.505 smd: 41(0,0)
QFN40#2
  round 0.5 smd: (-3.3,3.3) (6.475,-5.332)
  oval 0.203x0.762 smd: 1(-1.8,-2.405) 2(-1.4,-2.405) 3(-1,-2.405) 4(-0.6,-2.405) 5(-0.2,-2.405) 6(0.2,-2.405) 7(0.6,-2.405) 8(1,-2.405) 9(1.4,-2.405) 10(1.8,-2.405) 21(1.8,2.405) 22(1.4,2.405) 23(1,2.405) 24(0.6,2.405) 25(0.2,2.405) 26(-0.2,2.405) 27(-0.6,2.405) 28(-1,2.405) 29(-1.4,2.405) 30(-1.8,2.405)
  oval 0.762x0.203 smd: 11(2.405,-1.8) 12(2.405,-1.4) 13(2.405,-1) 14(2.405,-0.6) 15(2.405,-0.2) 16(2.405,0.2) 17(2.405,0.6) 18(2.405,1) 19(2.405,1.4) 20(2.405,1.8) 31(-2.405,1.8) 32(-2.405,1.4) 33(-2.405,1) 34(-2.405,0.6) 35(-2.405,0.2) 36(-2.405,-0.2) 37(-2.405,-0.6) 38(-2.405,-1) 39(-2.405,-1.4) 40(-2.405,-1.8)
  rect 3.505x3.505 smd: 41(0,0)
QFP100-20-1414
  rect 0.254x1.524 smd: 1(-6,-7.75) 2(-5.5,-7.75) 3(-5,-7.75) 4(-4.5,-7.75) 5(-4,-7.75) 6(-3.5,-7.75) 7(-3,-7.75) 8(-2.5,-7.75) 9(-2,-7.75) 10(-1.5,-7.75) 11(-1,-7.75) 12(-0.5,-7.75) 13(0,-7.75) 14(0.5,-7.75) 15(1,-7.75) 16(1.5,-7.75) 17(2,-7.75) 18(2.5,-7.75) 19(3,-7.75) 20(3.5,-7.75) 21(4,-7.75) 22(4.5,-7.75) 23(5,-7.75) 24(5.5,-7.75) 25(6,-7.75) 51(6,7.75) 52(5.5,7.75) 53(5,7.75) 54(4.5,7.75) 55(4,7.75) 56(3.5,7.75) 57(3,7.75) 58(2.5,7.75) 59(2,7.75) 60(1.5,7.75) 61(1,7.75) 62(0.5,7.75) 63(0,7.75) 64(-0.5,7.75) 65(-1,7.75) 66(-1.5,7.75) 67(-2,7.75) 68(-2.5,7.75) 69(-3,7.75) 70(-3.5,7.75) 71(-4,7.75) 72(-4.5,7.75) 73(-5,7.75) 74(-5.5,7.75) 75(-6,7.75)
  rect 1.524x0.254 smd: 26(7.75,-6) 27(7.75,-5.5) 28(7.75,-5) 29(7.75,-4.5) 30(7.75,-4) 31(7.75,-3.5) 32(7.75,-3) 33(7.75,-2.5) 34(7.75,-2) 35(7.75,-1.5) 36(7.75,-1) 37(7.75,-0.5) 38(7.75,0) 39(7.75,0.5) 40(7.75,1) 41(7.75,1.5) 42(7.75,2) 43(7.75,2.5) 44(7.75,3) 45(7.75,3.5) 46(7.75,4) 47(7.75,4.5) 48(7.75,5) 49(7.75,5.5) 50(7.75,6) 76(-7.75,6) 77(-7.75,5.5) 78(-7.75,5) 79(-7.75,4.5) 80(-7.75,4) 81(-7.75,3.5) 82(-7.75,3) 83(-7.75,2.5) 84(-7.75,2) 85(-7.75,1.5) 86(-7.75,1) 87(-7.75,0.5) 88(-7.75,0) 89(-7.75,-0.5) 90(-7.75,-1) 91(-7.75,-1.5) 92(-7.75,-2) 93(-7.75,-2.5) 94(-7.75,-3) 95(-7.75,-3.5) 96(-7.75,-4) 97(-7.75,-4.5) 98(-7.75,-5) 99(-7.75,-5.5) 100(-7.75,-6)
R0402
  rect 0.635x0.508 smd: 1(-0.508,0) 2(0.508,0)
R0603
  rect 0.762x0.813 smd: 1(-0.762,0) 2(0.762,0)
R1206
  rect 1.397x1.651 smd: 1(-1.397,0) 2(1.397,0)
RJ8-0102SRFZ
  round 3.302 hole 3.302 unplated: (-12.7,0) (12.7,0)
  rect 1.422x1.422 hole 0.914: 1(-11.43,6.35) 9(2.54,6.35)
  round 1.422 hole 0.914: 2(-10.16,8.89) 3(-8.89,6.35) 4(-7.62,8.89) 5(-6.35,6.35) 6(-5.08,8.89) 7(-3.81,6.35) 8(-2.54,8.89) 10(3.81,8.89) 11(5.08,6.35) 12(6.35,8.89) 13(7.62,6.35) 14(8.89,8.89) 15(10.16,6.35) 16(11.43,8.89)
  round 2.134 hole 1.626: 19(-15.43,-4.572) 20(15.43,-4.572) 21(0,10.24)
SC0402
  custom 0.127x0.127 smd: 1(-0.508,0) 2(0.508,0)
SC-70-5
  rect 0.356x0.864 smd: 1(-0.65,-1) 2(0,-1) 3(0.65,-1) 4(0.65,1) 5(-0.65,1)
SD-MICRO
  round 1.016 hole 1.016 unplated: (-4.93,0) (3.05,0)
  rect 0.711x1.6 smd: 1(2.25,10.5) 2(1.15,10.5) 3(0.05,10.5) 4(-1.05,10.5) 5(-2.15,10.5) 6(-3.25,10.5) 7(-4.35,10.5) 8(-5.45,10.5) 9(-6.55,10.5)
  rect 1.194x1.422 smd: 10(-7.7,10)
  rect 1.194x2.21 smd: 11(-7.75,0.4) 12(7.75,0.4)
  rect 1.6x1.422 smd: 13(6.9,10)
SO8
  rect 0.635x1.778 smd: 1(-1.905,-2.594) 2(-0.635,-2.594) 3(0.635,-2.594) 4(1.905,-2.594) 5(1.905,2.594) 6(0.635,2.594) 7(-0.635,2.594) 8(-1.905,2.594)
SOIC8
  rect 0.635x1.778 smd: 1(-1.905,-2.594) 2(-0.635,-2.594) 3(0.635,-2.594) 4(1.905,-2.594) 5(1.905,2.594) 6(0.635,2.594) 7(-0.635,2.594) 8(-1.905,2.594)
SOT23-6
  rect 0.635x1.27 smd: 1(-0.95,-1.25) 2(0,-1.25) 3(0.95,-1.25) 4(0.95,1.25) 5(0,1.25) 6(-0.95,1.25)
TFM48-40-480
  rect 0.635x1.727 smd: 1(-11.684,-7.08) 2(-10.668,-7.08) 3(-9.652,-7.08) 4(-8.636,-7.08) 5(-7.62,-7.08) 6(-6.604,-7.08) 7(-5.588,-7.08) 8(-4.572,-7.08) 9(-3.556,-7.08) 10(-2.54,-7.08) 11(-1.524,-7.08) 12(-0.508,-7.08) 13(0.508,-7.08) 14(1.524,-7.08) 15(2.54,-7.08) 16(3.556,-7.08) 17(4.572,-7.08) 18(5.588,-7.08) 19(6.604,-7.08) 20(7.62,-7.08) 21(8.636,-7.08) 22(9.652,-7.08) 23(10.668,-7.08) 24(11.684,-7.08) 25(11.684,7.08) 26(10.668,7.08) 27(9.652,7.08) 28(8.636,7.08) 29(7.62,7.08) 30(6.604,7.08) 31(5.588,7.08) 32(4.572,7.08) 33(3.556,7.08) 34(2.54,7.08) 35(1.524,7.08) 36(0.508,7.08) 37(-0.508,7.08) 38(-1.524,7.08) 39(-2.54,7.08) 40(-3.556,7.08) 41(-4.572,7.08) 42(-5.588,7.08) 43(-6.604,7.08) 44(-7.62,7.08) 45(-8.636,7.08) 46(-9.652,7.08) 47(-10.668,7.08) 48(-11.684,7.08)
TPAD
  round 1.016 smd: 1(0,0)
TSOP-II-54
  rect 0.406x1.651 smd: 1(-10.4,-5.63) 2(-9.6,-5.63) 3(-8.8,-5.63) 4(-8,-5.63) 5(-7.2,-5.63) 6(-6.4,-5.63) 7(-5.6,-5.63) 8(-4.8,-5.63) 9(-4,-5.63) 10(-3.2,-5.63) 11(-2.4,-5.63) 12(-1.6,-5.63) 13(-0.8,-5.63) 14(0,-5.63) 15(0.8,-5.63) 16(1.6,-5.63) 17(2.4,-5.63) 18(3.2,-5.63) 19(4,-5.63) 20(4.8,-5.63) 21(5.6,-5.63) 22(6.4,-5.63) 23(7.2,-5.63) 24(8,-5.63) 25(8.8,-5.63) 26(9.6,-5.63) 27(10.4,-5.63) 28(10.4,5.63) 29(9.6,5.63) 30(8.8,5.63) 31(8,5.63) 32(7.2,5.63) 33(6.4,5.63) 34(5.6,5.63) 35(4.8,5.63) 36(4,5.63) 37(3.2,5.63) 38(2.4,5.63) 39(1.6,5.63) 40(0.8,5.63) 41(0,5.63) 42(-0.8,5.63) 43(-1.6,5.63) 44(-2.4,5.63) 45(-3.2,5.63) 46(-4,5.63) 47(-4.8,5.63) 48(-5.6,5.63) 49(-6.4,5.63) 50(-7.2,5.63) 51(-8,5.63) 52(-8.8,5.63) 53(-9.6,5.63) 54(-10.4,5.63)
TSOT-23-5
  rect 0.635x1.27 smd: 1(-0.95,-1.25) 2(0,-1.25) 3(0.95,-1.25) 4(0.95,1.25) 5(-0.95,1.25)
TSSOP-20
  rect 0.356x1.524 smd: 1(-2.925,-3) 2(-2.275,-3) 3(-1.625,-3) 4(-0.975,-3) 5(-0.325,-3) 6(0.325,-3) 7(0.975,-3) 8(1.625,-3) 9(2.275,-3) 10(2.925,-3) 11(2.925,3) 12(2.275,3) 13(1.625,3) 14(0.975,3) 15(0.325,3) 16(-0.325,3) 17(-0.975,3) 18(-1.625,3) 19(-2.275,3) 20(-2.925,3)
unnamed#2
  round 0.813 hole 0.813 unplated: (-2.5,1.18) (-1.25,1.18) (0,1.18) (1.25,1.18) (2.5,1.18)
unnamed#3
  round 0.813 hole 0.813 unplated: (-2.5,1.18) (-2.5,-1.18) (-1.25,1.18) (-1.25,-1.18) (0,1.18) (0,-1.18) (1.25,1.18) (1.25,-1.18) (2.5,1.18) (2.5,-1.18)
unnamed#4
  round 1.016 smd: (-10,-1.5) (-10,-1.5)
  round 2.032 hole 2.032 unplated: (-5,-2.5)
unnamed#5
  round 1.016 smd: (-15,1.5) (-15,1.5)
  round 2.032 hole 2.032 unplated: (-5,2.5)
unnamed#6
  round 2.032 hole 2.032 unplated: (5,2.5)
  round 1.016 smd: (10,1.5) (10,1.5)
unnamed#7
  round 1.016 smd: 1(0,0)

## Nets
A2V5: C243.1 C256.1 C257.1 C276.1 C277.1 J1.4 P1.F5 P1.F12 P1.L5 P1.L12 R12.2 R164.2 U6.5 U25.5
D1V2: C239.1 C240.1 C258.1 C259.1 C260.1 C261.1 L8.2 P1.D4 P1.D13 P1.F7 P1.F11 P1.G6 P1.G7 P1.G8 P1.G9 P1.G10 P1.H6 P1.H11 P1.J6 P1.K7 P1.K11 P1.N4 P1.N13 U24.5
D3V3: C5.1 C6.1 C7.1 C8.1 C9.1 C10.1 C28.2 C29.1 C30.1 C31.1 C32.1 C33.1 C34.1 C35.1 C36.1 C37.1 C38.1 C238.1 C241.1 C244.2 C245.2 C246.2 C247.2 C248.2 C253.2 C254.1 C255.1 C262.1 C263.1 C264.1 C265.1 C266.1 C267.1 C268.1 C269.1 C270.1 C271.1 C274.1 C275.1 C282.1 C283.1 C284.1 C285.1 C286.1 C287.1 C288.1 C289.1 D1.1 D2.1 D38.1 J3.4 J4.4 J6.2 L1.2 L10.2 P1.A1 P1.A16 P1.C4 P1.C7 P1.C10 P1.C13 P1.E3 P1.E14 P1.G3 P1.G14 P1.K3 P1.K14 P1.M3 P1.M14 P1.P4 P1.P7 P1.P10 P1.P13 P1.T1 P1.T16 R4.1 R5.1 R16.2 R17.2 R18.2 R94.1 R129.1 R137.1 R138.1 R139.1 R140.1 R141.1 R142.2 U5.1 U5.3 U5.9 U5.14 U5.27 U5.43 U5.49 U7.3 U7.7 U7.8 U24.1 U24.4 U25.1 U25.3 U26.6 U26.11 U26.28 U26.50 U26.75 U26.100 U27.1 U27.20 U28.1 U28.20 U29.1 U29.20 U30.1 U30.20 U31.1 U31.20 U32.1 U32.20 U33.1 U33.20 U34.1 U34.20 X4.1 X4.4
GND: C1.2 C2.2 C5.2 C6.2 C7.2 C8.2 C9.2 C10.2 C11.1 C28.1 C29.2 C30.2 C31.2 C32.2 C33.2 C34.2 C35.2 C36.2 C37.2 C38.2 C39.1 C40.1 C41.1 C42.1 C43.2 C44.2 C45.2 C46.2 C47.2 C48.2 C49.2 C50.2 C51.2 C52.2 C53.2 C54.2 C55.2 C56.2 C57.2 C58.2 C59.2 C60.2 C226.1 C227.1 C228.1 C229.1 C230.1 C231.1 C232.1 C233.1 C238.2 C239.2 C240.2 C241.2 C242.2 C243.2 C244.1 C245.1 C246.1 C247.1 C248.1 C251.1 C252.1 C253.1 C254.2 C255.2 C256.2 C257.2 C258.2 C259.2 C260.2 C261.2 C262.2 C263.2 C264.2 C265.2 C266.2 C267.2 C268.2 C269.2 C270.2 C271.2 C274.2 C275.2 C276.2 C277.2 C278.2 C279.2 C280.2 C281.2 C282.2 C283.2 C284.2 C285.2 C286.2 C287.2 C288.2 C289.2 D4.1 D26.2 J1.2 J1.10 J3.1 J4.6 J6.3 J7.3 J8.4 J8.8 J8.16 J11.4 J11.8 J11.16 J12.4 J12.8 J12.16 J13.4 J13.8 J13.16 J15.3 J15.4 P1.B2 P1.B15 P1.C5 P1.C12 P1.D7 P1.D10 P1.E2 P1.E4 P1.E5 P1.E12 P1.E13 P1.F6 P1.F10 P1.G4 P1.G12 P1.G13 P1.H7 P1.H8 P1.H9 P1.H10 P1.H13 P1.H15 P1.H16 P1.J3 P1.J7 P1.J8 P1.J9 P1.J10 P1.J11 P1.K4 P1.K8 P1.K13 P1.M4 P1.M5 P1.M12 P1.M13 P1.N7 P1.N10 P1.P5 P1.P12 P1.R2 P1.R15 R2.2 R3.1 R11.1 R31.2 R33.2 R73.1 R76.1 R77.1 R89.1 R90.1 R92.1 R95.1 R97.1 R99.1 R101.1 R105.1 R106.1 R107.1 R108.1 R130.2 R131.1 R135.1 R154.2 R155.2 R156.2 R157.2 U1.4 U5.6 U5.12 U5.28 U5.41 U5.46 U5.52 U5.54 U6.2 U7.4 U8.41 U9.41 U24.2 U25.2 U26.10 U26.19 U26.20 U26.27 U26.49 U26.74 U26.99 U27.10 U27.19 U28.10 U28.19 U29.10 U29.19 U30.10 U30.19 U31.10 U31.19 U32.10 U32.19 U33.10 U33.19 U34.10 U34.19 X4.2 Y1.2 Y1.4 Y2.2 Y2.4
GND_EARTH: C236.1 C278.1 C292.1 H1.1 J2.19 J2.20 R154.1
VCC_5V: C1.1 D4.2 J6.1 J15.1 J15.2 R1.2 U1.2
VDDIO_A_RGMII: C44.1 R91.1 R96.1 R103.1 R120.1 U8.27
VDDIO_B_RGMII: C46.1 R93.1 R98.1 R104.1 R122.1 U9.27
AB16: P1.A10 U26.58
AB17: P1.B11 U26.59
AB18: P1.A11 U26.60
AB19: P1.F3 U26.2
ARM_CLK: P1.D3 U26.12
AS_DAT0: P1.H2 R13.1
ASDO: P1.C1 U7.5
CAN_RX: J6.5 U26.70
CAN_TX: J6.4 U26.71
CLK_25M: P1.E1 X4.3
CONF_DONE: P1.H14 R18.1
DB0: P1.B12 U26.61
DB1: P1.A12 U26.62
DB2: P1.B7 U26.81
DB3: P1.A6 U26.82
DB4: P1.B1 U26.38
DB5: P1.A2 U26.39
DB6: P1.B3 U26.40
DB7: P1.A3 U26.41
DB8: P1.B4 U26.42
DB9: P1.A4 U26.43
DB10: P1.B5 U26.44
DB11: P1.A5 U26.45
DB12: P1.B6 U26.46
DB13: P1.A7 U26.55
DB14: P1.C8 U26.56
DB15: P1.B10 U26.57
DCLK: P1.H1 U7.6
ENET_AVDD_3.3: C59.1 C60.1 FB3.2 U8.14 U9.14
ENET_DVDD_3.3: C57.1 C58.1 FB3.1 R94.2 R146.1 R147.1 R148.1 R149.1 U8.3 U9.3
ENETA_AVDD_1.1: C47.1 C48.1 C51.1 FB1.2 U8.6 U8.11 U8.17
ENETA_DVDD_1.1: C49.1 C50.1 FB1.1 L6.1 U8.38
ENETA_DVDD_2.5: C43.1 R100.1 R120.2 R123.1 R124.1 R125.1 R126.1 U8.8
ENETA_GTX_CLK: P1.P14 R39.1
ENETA_INTN: P1.K12 R125.2 U8.20
ENETA_LED_1000: R56.1 R76.2 R100.2 U8.22
ENETA_LED_ACT: R51.1 R73.2 R90.2 U8.21
ENETA_MDC: P1.R16 R124.2 U8.40
ENETA_MDI_N0: U8.10 U23.23
ENETA_MDI_N1: U8.13 U23.20
ENETA_MDI_N2: U8.16 U23.17
ENETA_MDI_N3: U8.19 U23.14
ENETA_MDI_P0: U8.9 U23.24
ENETA_MDI_P1: U8.12 U23.21
ENETA_MDI_P2: U8.15 U23.18
ENETA_MDI_P3: U8.18 U23.15
ENETA_MDIO: P1.P15 R123.2 U8.39
ENETA_RESETN: P1.T15 R126.2 U8.1
ENETA_RX_CLK: P1.M15 R121.1
ENETA_RX_D0: P1.L15 R27.1
ENETA_RX_D1: P1.J12 R30.1
ENETA_RX_D2: P1.J14 R35.1
ENETA_RX_D3: P1.J13 R37.1
ENETA_RX_DV: P1.L16 R24.1
ENETA_TX_D0: P1.N14 R43.1
ENETA_TX_D1: P1.N16 R45.1
ENETA_TX_D2: P1.N15 R47.1
ENETA_TX_D3: P1.P16 R49.1
ENETA_TX_EN: P1.L14 R41.1
ENETB_AVDD_1.1: C54.1 C55.1 C56.1 FB2.2 U9.6 U9.11 U9.17
ENETB_DVDD_1.1: C52.1 C53.1 FB2.1 L7.1 U9.38
ENETB_DVDD_2.5: C45.1 R23.1 R26.1 R29.1 R34.1 R102.1 R122.2 U9.8
ENETB_GTX_CLK: P1.F14 R40.1
ENETB_INTN: P1.C11 R29.2 U9.20
ENETB_LED_1000: R60.1 R89.2 R102.2 U9.22
ENETB_LED_ACT: R52.1 R77.2 R92.2 U9.21
ENETB_MDC: P1.K15 R26.2 U9.40
ENETB_MDI_N0: U9.10 U23.11
ENETB_MDI_N1: U9.13 U23.8
ENETB_MDI_N2: U9.16 U23.5
ENETB_MDI_N3: U9.19 U23.2
ENETB_MDI_P0: U9.9 U23.12
ENETB_MDI_P1: U9.12 U23.9
ENETB_MDI_P2: U9.15 U23.6
ENETB_MDI_P3: U9.18 U23.3
ENETB_MDIO: P1.J16 R23.2 U9.39
ENETB_RESETN: P1.K16 R34.2 U9.1
ENETB_RX_CLK: P1.E15 R22.1
ENETB_RX_D0: P1.C15 R28.1
ENETB_RX_D1: P1.B16 R32.1
ENETB_RX_D2: P1.C14 R36.1
ENETB_RX_D3: P1.A15 R38.1
ENETB_RX_DV: P1.C16 R25.1
ENETB_TX_D0: P1.F15 R44.1
ENETB_TX_D1: P1.F16 R46.1
ENETB_TX_D2: P1.G15 R48.1
ENETB_TX_D3: P1.G16 R50.1
ENETB_TX_EN: P1.D16 R42.1
F_CLK: P1.F8 U26.84
F_NAD: P1.C3 U26.93
F_NBL0: P1.E6 U26.97
F_NBL1: P1.C2 U26.98
F_NCE2: P1.D5 U26.88
F_NWAIT: P1.E7 U26.87
GPIO: P1.K6 U26.15
HUB1_A: P1.T6 U28.7 U29.8
HUB1_B: P1.R6 U28.8 U29.6
HUB1_B1: P1.T2 R160.1 U27.5
HUB1_B2: P1.R4 R163.1 U27.2
HUB1_BUF_A: J8.9 U28.13
HUB1_BUF_B: J8.10 U28.12
HUB1_BUF_B1: J8.3 U27.15
HUB1_BUF_B2: J8.7 U27.18
HUB1_BUF_C: J8.11 U28.15
HUB1_BUF_CLK: J8.13 U28.17
HUB1_BUF_D: J8.12 U28.14
HUB1_BUF_G1: J8.2 U27.13
HUB1_BUF_G2: J8.6 U27.16
HUB1_BUF_LATCH: J8.14 U28.16
HUB1_BUF_OE: J8.15 U28.18
HUB1_BUF_R1: J8.1 U27.14
HUB1_BUF_R2: J8.5 U27.17
HUB1_C: P1.T7 U28.5 U29.7
HUB1_CLK: P1.R10 U28.3 U29.5
HUB1_D: P1.R7 U28.6 U29.4
HUB1_G1: P1.P1 R159.1 U27.7
HUB1_G2: P1.R3 R162.1 U27.4
HUB1_LATCH: P1.P9 U28.4 U29.2
HUB1_OE: P1.T10 U28.2 U29.3
HUB1_R1: P1.R1 R158.1 U27.6
HUB1_R2: P1.T3 R161.1 U27.3
HUB2_B1: P1.T12 U30.5
HUB2_B2: P1.R11 U30.7
HUB2_BUF_A: J11.9 U29.12
HUB2_BUF_B: J11.10 U29.14
HUB2_BUF_B1: J11.3 U30.15
HUB2_BUF_B2: J11.7 U30.13
HUB2_BUF_C: J11.11 U29.13
HUB2_BUF_CLK: J11.13 U29.15
HUB2_BUF_D: J11.12 U29.16
HUB2_BUF_G1: J11.2 U30.18
HUB2_BUF_G2: J11.6 U30.17
HUB2_BUF_LATCH: J11.14 U29.18
HUB2_BUF_OE: J11.15 U29.17
HUB2_BUF_R1: J11.1 U30.16
HUB2_BUF_R2: J11.5 U30.14
HUB2_G1: P1.R13 U30.2
HUB2_G2: P1.T13 U30.3
HUB2_R1: P1.R12 U30.4
HUB2_R2: P1.T11 U30.6
HUB3_A: P1.D11 U31.8 U33.2
HUB3_B: P1.E10 U31.7 U33.3
HUB3_B1: P1.L11 U32.4
HUB3_B2: P1.L13 U32.5
HUB3_BUF_A: J13.9 U31.12
HUB3_BUF_B: J13.10 U31.13
HUB3_BUF_B1: J13.3 U32.16
HUB3_BUF_B2: J13.7 U32.15
HUB3_BUF_C: J13.11 U31.14
HUB3_BUF_CLK: J13.13 U31.16
HUB3_BUF_D: J13.12 U31.15
HUB3_BUF_G1: J13.2 U32.13
HUB3_BUF_G2: J13.6 U32.18
HUB3_BUF_LATCH: J13.14 U31.18
HUB3_BUF_OE: J13.15 U31.17
HUB3_BUF_R1: J13.1 U32.14
HUB3_BUF_R2: J13.5 U32.17
HUB3_C: P1.D14 U31.6 U33.4
HUB3_CLK: P1.D12 U31.4 U33.6
HUB3_D: P1.D15 U31.5 U33.5
HUB3_G1: P1.G11 U32.7
HUB3_G2: P1.N11 U32.2
HUB3_LATCH: P1.F13 U31.2 U33.8
HUB3_OE: P1.E11 U31.3 U33.7
HUB3_R1: P1.J15 U32.6
HUB3_R2: P1.M11 U32.3
HUB4_B1: P1.D9 U34.4
HUB4_B2: P1.K9 U34.7
HUB4_BUF_A: J12.9 U33.18
HUB4_BUF_B: J12.10 U33.17
HUB4_BUF_B1: J12.3 U34.16
HUB4_BUF_B2: J12.7 U34.13
HUB4_BUF_C: J12.11 U33.16
HUB4_BUF_CLK: J12.13 U33.14
HUB4_BUF_D: J12.12 U33.15
HUB4_BUF_G1: J12.2 U34.17
HUB4_BUF_G2: J12.6 U34.14
HUB4_BUF_LATCH: J12.14 U33.12
HUB4_BUF_OE: J12.15 U33.13
HUB4_BUF_R1: J12.1 U34.18
HUB4_BUF_R2: J12.5 U34.15
HUB4_G1: P1.F9 U34.3
HUB4_G2: P1.E9 U34.6
HUB4_R1: P1.A14 U34.2
HUB4_R2: P1.C9 U34.5
MIIA_GTX_CLK: R39.2 U8.33
MIIA_RX_CLK: R91.2 R121.2 U8.31
MIIA_RX_D0: R27.2 R95.2 U8.29
MIIA_RX_D1: R30.2 R99.2 U8.28
MIIA_RX_D2: R35.2 R103.2 R105.2 U8.26
MIIA_RX_D3: R37.2 R96.2 U8.25
MIIA_RX_DV: R24.2 R107.2 U8.30
MIIA_TX_D0: R43.2 U8.34
MIIA_TX_D1: R45.2 U8.35
MIIA_TX_D2: R47.2 U8.36
MIIA_TX_D3: R49.2 U8.37
MIIA_TX_EN: R41.2 U8.32
MIIB_GTX_CLK: R40.2 U9.33
MIIB_RX_CLK: R22.2 R93.2 U9.31
MIIB_RX_D0: R28.2 R97.2 U9.29
MIIB_RX_D1: R32.2 R101.2 U9.28
MIIB_RX_D2: R36.2 R104.2 R106.2 U9.26
MIIB_RX_D3: R38.2 R98.2 U9.25
MIIB_RX_DV: R25.2 R108.2 U9.30
MIIB_TX_D0: R44.2 U9.34
MIIB_TX_D1: R46.2 U9.35
MIIB_TX_D2: R48.2 U9.36
MIIB_TX_D3: R50.2 U9.37
MIIB_TX_EN: R42.2 U9.32
NCONFIG: P1.H5 R17.1
NCSO: P1.D2 U7.1
NRST: C11.2 R5.2 U26.14
NSTATUS: P1.F4 R16.1
P0MDIA+: J2.1 U23.25
P0MDIA-: J2.2 U23.26
P0MDIB+: J2.3 U23.28
P0MDIB-: J2.6 U23.29
P0MDIC+: J2.4 U23.31
P0MDIC-: J2.5 U23.32
P0MDID+: J2.7 U23.34
P0MDID-: J2.8 U23.35
P1MDIA+: J2.9 U23.37
P1MDIA-: J2.10 U23.38
P1MDIB+: J2.11 U23.40
P1MDIB-: J2.14 U23.41
P1MDIC+: J2.12 U23.43
P1MDIC-: J2.13 U23.44
P1MDID+: J2.15 U23.46
P1MDID-: J2.16 U23.47
PHYA-GREEN: D37.2 R56.2
PHYA-YELLOW: D36.2 R51.2
PHYB-GREEN: D35.2 R60.2
PHYB-YELLOW: D34.2 R52.2
RD: P1.D6 U26.85
RS485_DE: J6.8 U26.52
RS485_RE: J6.7 U26.51
RS485_RX: J6.6 U26.48
RS485_TX: J6.9 U26.47
SD_A0: P1.F1 U5.23
SD_A1: P1.G2 U5.24
SD_A2: P1.J1 U5.25
SD_A3: P1.G1 U5.26
SD_A4: P1.N5 U5.29
SD_A5: P1.T5 U5.30
SD_A6: P1.R5 U5.31
SD_A7: P1.N6 U5.32
SD_A8: P1.P6 U5.33
SD_A9: P1.M7 U5.34
SD_A10: P1.J2 U5.22
SD_A11: P1.P8 U5.35
SD_BA0: P1.K2 U5.20
SD_BA1: P1.K1 U5.21
SD_CAS: P1.F2 U5.17
SD_CKE: P1.M6 U5.37
SD_CLK: P1.T4 U5.38
SD_CS: P1.L1 U5.19
SD_D0: P1.P3 U5.2
SD_D1: P1.N3 U5.4
SD_D2: P1.P2 U5.5
SD_D3: P1.L6 U5.7
SD_D4: P1.N2 U5.8
SD_D5: P1.L4 U5.10
SD_D6: P1.L3 U5.11
SD_D7: P1.N1 U5.13
SD_D8: P1.M8 U5.42
SD_D9: P1.L8 U5.44
SD_D10: P1.L9 U5.45
SD_D11: P1.N9 U5.47
SD_D12: P1.M9 U5.48
SD_D13: P1.L10 U5.50
SD_D14: P1.P11 U5.51
SD_D15: P1.T14 U5.53
SD_DQ0: P1.L2 U5.15
SD_DQ1: P1.N8 U5.39
SD_RAS: P1.K5 U5.18
SD_WE: P1.D1 U5.16
SWCLK: J3.2 R129.2 U26.76
SWDIO: J3.3 R130.1 U26.72
TCK: J1.1 P1.H3 R11.2 U6.1
TDI: J1.9 P1.H4 U6.3
TDO: J1.3 P1.J4 U6.6
TF_CLK: J4.5 R163.2 U26.80
TF_CMD: J4.3 R139.2 R162.2 U26.83
TF_DATA0: J4.7 R138.2 R158.2 U26.65
TF_DATA1: J4.8 R137.2 R159.2 U26.66
TF_DATA2: J4.1 R141.2 R160.2 U26.78
TF_DATA3: J4.2 R140.2 R161.2 U26.79
TMS: J1.5 P1.J5 R12.1 U6.4
USART_RX: J7.2 U26.26
USART_TO_FPGA_RX: P1.A13 U26.69
USART_TO_FPGA_TX: P1.B13 U26.68
USART_TX: J7.1 U26.25
WR: P1.C6 U26.86
N00507: R1.1 U1.7
N00656: C2.1 U1.8
N00761: C3.2 R2.1
N00851: C3.1 U1.6
N00855: C4.1 L1.1 U1.3
N00885: C4.2 U1.1
N00957: R3.2 R4.2 U1.5
N59239: L6.2 U8.2
N59407: C41.2 U8.5 Y1.3
N59411: C39.2 U8.4 Y1.1
N59605: L7.2 U9.2
N59753: C42.2 U9.5 Y2.3
N59757: C40.2 U9.4 Y2.1
N68560: C226.2 U23.1
N68564: R111.1 U23.48
N68628: C227.2 U23.4
N68632: R112.1 U23.45
N68696: C228.2 U23.7
N68700: R113.1 U23.42
N68748: C229.2 U23.10
N68752: R114.1 U23.39
N68848: C230.2 U23.13
N68852: R115.1 U23.36
N68966: C231.2 U23.16
N68970: R116.1 U23.33
N69086: C232.2 U23.19
N69090: R117.1 U23.30
N69194: C233.2 U23.22
N69198: R118.1 U23.27
N70343: P1.H12 R164.1
N5916714: R31.1 U8.7
N5956514: R33.1 U9.7
N15733620: R127.2 U26.16
N15733628: R128.2 U26.17
N15733972: R131.2 U26.94
N15734280: C251.2 C252.2 L10.1 U26.21 U26.22
N15734652: R135.2 U26.37
N15801228: L8.1 U24.3
N15801432: C242.1 U25.4
N15813450: D26.1 R142.1
N15817579: R13.2 U7.2
N15925802: D37.1 R146.2
N15925882: D36.1 R147.2
N15925976: D35.1 R148.2
N15926055: D34.1 R149.2
N15962568: C279.1 H2.1 R155.1
N15964024: C280.1 H3.1 R156.1
N15964116: C281.1 H4.1 R157.1
N15994943: C292.2 R111.2 R112.2 R113.2 R114.2
N15995237: C236.2 R115.2 R116.2 R117.2 R118.2
N16105743: P1.E8 R165.1
N16105815: D38.2 R165.2
N157335061: D1.2 R128.1
N157335281: D2.2 R127.1

Pads without a net: J1 6 7 8; J2 21; J4 9 10 11 12 13; M1 1; M2 1; M3 1; M4 1; NOREF#35 1; NOREF#36 1; P1 A8 A9 B8 B9 B14 D8 E16 G5 K10 L7 M1 M2 M10 M16 N12 R8 R9 R14 T8 T9; U5 36 40; U8 23 24; U9 23 24; U26 1 3 4 5 7 8 9 13 18 23 24 29 30 31 32 33 34 35 36 53 54 63 64 67 73 77 89 90 91 92 95 96; U27 8 9 11 12; U28 9 11; U29 9 11; U30 8 9 11 12; U31 9 11; U32 8 9 11 12; U33 9 11; U34 8 9 11 12

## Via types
v1: diameter 0.559, hole 0.254, TOP to BOTTOM, 534 vias
v2: diameter 0.457, hole 0.203, TOP to BOTTOM, 13 vias
v3: diameter 0, hole 0, ART02 to BOTTOM, 1 via
v4: diameter 0.508, hole 0.254, TOP to BOTTOM, 2 vias

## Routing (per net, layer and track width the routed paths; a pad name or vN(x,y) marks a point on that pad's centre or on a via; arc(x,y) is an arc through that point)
A2V5: length 51.5
  TOP w0.381: v1(127.13,24.99) 126.37,24.23 v1(126.37,22.45) 127.13,21.69 127.13,18.94 J1.4 ; v1(86.91,30.66) 87.41,31.16 P1.L5 ; v1(80.91,30.66) 80.41,31.16 P1.L12 ; P1.F12 v1(79.91,25.66) ; P1.F5 v1(87.91,25.66)
  TOP w0.508: v1(106.68,1.62) v1(107.83,1.62) 108.84,2.64 108.84,6.07 113.29,10.51 113.29,11.83 114.13,12.67 119.38,12.67 121.92,10.13 126.24,10.13 127,10.89 127,16.1 125.65,17.45 J1.4
  BOTTOM w0.381: U6.5 v1(126.37,22.45) ; R12.2 v1(127.13,24.99) ; P1.L12 80.41,31.16 v1(80.91,30.66) ; 70.99,30.1 71.12,30.23 R164.2
D1V2: length 25.6
  TOP w0.381: P1.K11 81.41,30.16 v1(81.91,29.66) ; P1.G9 v1(82.91,26.66) ; P1.G6 v1(85.91,26.66) P1.G7 ; P1.F11 v1(81.91,26.66) P1.G10 ; v1(65.7,39.34) 65.7,38.58 65.31,38.2 60.11,38.2 59.02,39.29 U24.5 ; P1.N13 v1(79.91,33.66) ; P1.D13 v1(79.91,23.66) ; P1.H11 v1(80.91,27.66) ; P1.N4 v1(88.91,33.66) ; P1.H6 v1(86.91,27.66) ; P1.G8 v1(84.91,26.66) P1.F7 ; P1.K7 v1(85.91,30.66) ; P1.D4 v1(88.91,24.66) ; P1.J6 v1(85.91,29.66)
  BOTTOM w0.381: v1(85.91,26.66) 85.43,27.15 C260.1 ; C258.1 P1.G10 v1(82.91,26.66) ; v1(85.91,29.66) 85.43,29.18 C261.1 ; C259.1 v1(81.91,29.66)
  vias: v1(64.55,40.48) v1(64.55,39.34) v1(65.7,40.48)
D3V3: length 146
  TOP w0.229: v1(103,26.26) 102.57,26.69 U26.28 ; U26.75 115.35,14.86 v1(115.7,15.21) ; v1(103,16.1) 102.87,16.1 102.46,15.69 U26.50 ; U26.11 110.35,30.59 v1(110.11,30.83) ; U26.6 v1(112.85,30.77) ; v1(115.83,28.16) 116.31,27.69 U26.100
  TOP w0.305: U30.1 v1(78.14,44.04) ; U28.1 v1(85.86,44.11) ; U27.1 v1(94.4,44.11) ; U29.1 v1(70.77,44.09) ; U29.20 70.77,47.57 v1(70.62,47.42) ; v1(77.98,47.52) 78.14,47.67 U30.20
  TOP w0.381: P1.T16 v1(75.91,35.66) ; v1(85.6,47.54) 85.86,47.8 U28.20 ; C286.1 v1(60.84,10.31) ; P1.P13 79.41,34.16 v1(78.91,34.66) ; U7.3 v1(99.32,34.39) ; C289.1 v1(88.9,10.28) ; C32.1 119.89,34.64 v1(119.93,34.68) ; P1.C10 v1(81.91,22.66) ; P1.C4 v1(88.91,22.66) ; P1.P10 82.41,34.16 v1(81.91,34.66) ; v1(121.53,34.65) 121.54,34.64 C34.1 ; D1.1 v1(114.43,6.57) ; v1(69.22,7.72) 69.35,7.84 C287.1 ; C288.1 81.33,10.36 v1(81.41,10.28) ; D2.1 v1(116.08,6.57) ; v1(115.64,34.7) 115.67,34.67 C30.1 ; X4.1 X4.4 98.64,25.33 C274.1 97.92,24.99 v1(97.41,25.5) ; P1.C13 v1(78.91,22.66) ; P1.K3 v1(89.91,30.66) ; P1.G3 v1(89.91,26.66) ; P1.A1 v1(90.91,20.66) ; P1.E3 v1(89.91,24.66) ; D38.1 v1(98.42,11.56) ; R4.1 27.69,56.36 29.47,58.14 34.68,58.14 35.06,57.75 v1(35.06,57.12) ; R139.1 v1(107.83,44.17) ; U7.7 107.31,35.66 107.57,35.4 C28.2 ; P1.P4 v1(88.91,34.66) ; P1.G14 v1(77.91,26.66) ; v1(77.88,30.66) 77.91,30.66 78.41,30.16 P1.K14 ; U24.1 v1(62.66,42.71) ; R137.1 R138.1 v1(108.21,39.59) ; C28.2 108.46,34.89 v1(108.08,34.51) 108.84,33.75 R5.1 ; C28.2 108.46,36.04 107.57,36.93 U7.8 ; U27.20 94.4,47.83 v1(94.11,47.54) ; P1.T1 v1(91.91,36.66) ; J4.4 v1(111.13,43.14) ; P1.P7 v1(85.91,34.66) ; P1.A16 v1(75.91,20.66) ; P1.E14 v1(77.91,24.66) ; R140.1 R141.1 108.21,47.59 107.94,47.86 v1(107.94,48.74) ; C29.1 v1(112.15,34.64) ; R142.2 31.37,56.61 ; R129.1 v1(123.32,26.89) ; P1.M14 v1(78.91,31.66) ; P1.C7 v1(85.91,22.66) ; P1.M3 v1(89.91,32.66)
  BOTTOM w0.254: v1(81.91,34.66) 81.91,35.03 81.67,35.28 81.67,36.8 v1(80.9,37.56)
  BOTTOM w0.305: U34.20 81.63,10.07 v1(81.41,10.28) ; U31.1 v1(69.21,13.69) ; v1(88.9,10.28) 89.12,10.07 U33.20 ; U34.1 v1(81.63,13.79) ; v1(69.22,7.72) 69.21,7.73 U31.20 ; 61.09,9.03 61.09,10.06 v1(60.84,10.31) ; U25.3 68.82,31.48 69.09,31.21 69.09,30.07 68.84,29.81 68.46,29.81 ; U33.1 v1(89.12,13.79) ; 61.09,15.03 v1(61.09,13.69)
  BOTTOM w0.381: v1(37.5,45.69) R94.1 v1(38.52,46.71) ; R16.2 89.76,26.81 v1(89.91,26.66) 90.58,26.66 R17.2 ; R18.2 66.17,25.97 v1(66.19,25.99) ; C268.1 90.77,20.8 v1(90.91,20.66) ; v1(70.62,47.42) 70.71,47.51 C285.1 ; v1(113.54,49.25) C33.1 112.73,49.2 U5.43 ; C283.1 85.57,47.57 v1(85.6,47.54) ; v1(77.88,30.66) 77.87,30.68 C270.1 ; C275.1 v1(97.41,25.5) ; C245.2 v1(115.83,28.16) ; v1(77.91,24.66) 77.85,24.61 C269.1 ; v1(35.06,55.85) 35.15,55.76 C7.1 ; U5.14 111.13,35.15 111.64,34.64 v1(112.15,34.64) ; C271.1 78.87,34.7 v1(78.91,34.66) ; U5.9 115.13,35.21 v1(115.64,34.7) ; v1(78.91,22.66) 78.87,22.62 C264.1 ; C255.1 91.83,36.75 v1(91.91,36.66) ; C266.1 81.03,37.69 v1(80.9,37.56) ; U5.49 117.53,49.48 C35.1 117.51,50.36 v1(117.48,50.39) ; U5.1 v1(121.53,34.65) ; U5.27 100.73,34.91 C31.1 99.45,34.26 v1(99.32,34.39) ; C282.1 93.98,47.42 v1(94.11,47.54) ; C248.2 102.75,26 v1(103,26.26) ; C8.1 36.04,55.56 v1(36.33,55.85) ; C37.1 v1(107.07,16.23) ; C253.2 113.03,30.59 v1(112.85,30.77) ; C263.1 88.9,34.67 v1(88.91,34.66) ; C267.1 89.98,24.73 v1(89.91,24.66) ; C9.1 34.26,55.56 ; C254.1 75.95,20.62 v1(75.91,20.66) ; C262.1 75.82,35.75 v1(75.91,35.66) ; C38.1 v1(83.06,17.5) ; C247.2 115.83,15.08 v1(115.7,15.21) ; C244.2 v1(103,16.1) ; U5.3 v1(119.93,34.68) ; C284.1 v1(77.98,47.52) ; C265.1 81.91,21.95 v1(81.91,22.66) ; L10.2 v1(111.04,32.39) ; C246.2 v1(110.11,30.83) ; C10.1 33.37,55.56 ; C36.1 v1(111.51,27.66)
  vias: v1(33.79,57.12) v1(33.79,55.85) v1(36.33,57.12) v1(37.6,57.12) v1(37.6,55.85) v1(55.41,45.69) v1(55.41,44.55) v1(56.42,45.69) v1(57.44,45.69) v1(64.27,30.07) v1(65.16,30.07)
GND: length 276.6
  TOP w0.229: v1(103.13,27.06) 103,27.19 U26.27 ; U26.10 110.85,30.68 v1(111,30.83) ; v1(107.07,30.83) 106.81,30.83 106.35,30.37 U26.19 ; U26.49 100.29,16.19 v1(100.21,16.1) ; v1(105.92,30.83) 105.85,30.76 U26.20 ; U26.99 v1(115.85,27.19) ; U26.74 v1(114.85,15.21)
  TOP w0.305: U28.10 v1(91.71,44.11) ; v1(71.63,47.42) 71.42,47.63 U29.19 ; U27.10 v1(100.25,44.11) ; U30.10 v1(83.99,44.11) ; v1(79,47.52) 78.79,47.73 U30.19 ; U29.10 76.62,44 v1(76.46,44.17) ; C41.1 43.34,44.17 v1(43.34,45.69) 43.34,46.71 43.56,46.92 Y1.2 44.53,47.85 44.78,48.1 v1(45.88,48.1) 47.66,48.1 47.86,47.9 47.86,45.51 47.57,45.22 Y1.4 46.73,44.55 47.15,44.12 C39.1 47.15,43.53 v1(47.79,42.9)
  TOP w0.381: R108.1 v1(53.63,17.24) ; P1.G12 v1(79.91,27.66) P1.H13 ; v1(29.6,52.93) 29.47,53.06 D26.2 ; P1.M4 v1(88.91,32.66) ; P1.H8 v1(84.91,27.66) ; v1(61.98,10.31) 61.85,10.43 C286.2 ; v1(117.99,28.29) 118.24,28.04 R131.1 ; v1(43.7,32.18) 43.7,32.76 R73.1 ; P1.R15 77.41,35.16 v1(76.91,35.66) ; P1.G13 v1(78.91,26.66) ; R97.1 v1(56.81,14.19) ; P1.M13 79.41,32.16 v1(78.91,32.66) ; P1.E5 v1(87.91,24.66) P1.E4 ; R106.1 v1(47.41,15.21) ; U28.19 v1(86.51,47.56) ; C34.2 v1(122.31,32.74) ; R107.1 v1(50.96,33.12) ; P1.G4 v1(87.91,26.66) ; P1.J7 v1(84.91,29.66) P1.J8 ; P1.E13 v1(78.91,24.66) ; P1.H7 v1(85.91,27.66) ; P1.E12 v1(79.91,24.66) ; v1(79.91,32.66) 80.41,32.16 P1.M12 ; v1(82.43,10.28) 82.35,10.36 C288.2 ; C28.1 109.48,35.28 v1(110.11,34.64) ; R33.2 v1(43.09,28.42) ; X4.2 95.88,27.78 v1(95.13,27.78) ; R130.2 v1(123.32,32.61) ; v1(42.2,32.18) 42.2,32.86 R90.1 ; C50.2 v1(54.14,45.31) ; P1.J11 81.41,29.16 v1(80.91,29.66) ; C2.2 v1(18.77,47.5) ; R101.1 v1(53.5,14.83) ; P1.R2 v1(90.91,35.66) ; v1(75.7,28.04) 75.82,28.16 P1.H16 P1.H15 ; C11.1 v1(109.86,33.88) ; P1.J3 v1(88.91,29.66) ; P1.B15 v1(77.91,21.66) ; P1.J9 83.41,29.16 v1(82.91,29.66) P1.J10 ; P1.M5 v1(87.91,32.66) ; R135.1 v1(97.03,22.32) ; R89.1 v1(41.01,15.97) ; C287.2 70.36,7.97 v1(70.11,7.72) ; P1.P5 v1(87.91,34.66) ; P1.H10 v1(81.91,27.66) ; R92.1 v1(38.34,14.83) ; P1.N10 82.41,33.16 v1(81.91,33.66) ; C53.2 v1(55.15,27.4) ; P1.K4 v1(88.91,30.66) ; v1(89.91,25.66) 90.41,25.16 P1.E2 ; v1(79.91,34.66) 80.41,34.16 P1.P12 ; R76.1 44.11,29.43 v1(43.85,29.18) ; C274.2 95.89,25.12 v1(95.89,25.5) ; R31.2 41.34,44.67 v1(40.96,45.05) ; J4.6 v1(111.21,40.94) ; R99.1 v1(50.84,30.45) ; P1.N7 v1(85.91,33.66) ; v1(21.54,49.99) 21.04,49.99 R2.2 ; v1(78.91,30.66) 79.41,30.16 P1.K13 ; C52.2 v1(56.17,26) ; P1.C5 v1(87.91,22.66) ; P1.F10 v1(81.91,25.66) ; R95.1 v1(56.17,30.45) ; U27.19 v1(95.05,47.49) ; R105.1 v1(47.41,32.74) ; P1.H9 v1(82.91,27.66) ; C42.1 v1(43.93,25.62) 43.93,26 44.23,26.31 v1(44.23,28.04) 44.23,28.54 44.57,28.89 Y2.2 45.42,29.6 45.76,29.94 v1(46.65,29.94) 48.47,29.94 48.8,29.61 v1(48.8,28.04) 48.8,27.44 48.55,27.19 Y2.4 47.62,26.3 48.04,25.88 C40.1 ; C41.1 43.85,43.3 v1(44.23,42.92) ; U7.4 99.45,33.12 v1(99.32,33.25) ; P1.F6 v1(85.91,25.66) ; P1.D7 v1(85.91,23.66) ; R77.1 v1(38.34,15.97) ; C32.2 v1(120.65,32.74) ; P1.B2 v1(89.91,22.66) ; C30.2 v1(114.65,32.74) ; C29.2 v1(112.15,31.72) ; C289.2 v1(89.92,10.28) ; R3.1 v1(23.12,55.09) ; P1.C12 v1(79.91,22.66) ; P1.D10 v1(81.91,23.66) ; C49.2 v1(55.15,43.66) ; P1.K8 v1(84.91,30.66)
  ART02 w0.381: J13.16 64.01,5.77 ; J13.16 61.77,5.77 ; J13.16 62.89,4.65 ; J13.16 62.89,6.89 ; 52.73,4.65 J13.8 ; J13.8 52.73,6.89 ; J13.8 51.61,5.77 ; J13.8 53.85,5.77 ; J11.8 56.39,54.23 ; J11.8 55.27,55.35 ; J11.8 55.27,53.11 ; J11.8 54.15,54.23 ; 87.65,4.65 J12.4 ; J12.4 88.77,5.77 ; J12.4 87.65,6.89 ; J12.4 86.53,5.77 ; J6.3 14,2.89 ; J6.3 13.49,1.75 13.08,2.16 ; J6.3 14.94,1.75 ; J8.16 85.11,55.35 ; J8.16 85.11,53.11 ; J8.16 86.23,54.23 ; J8.16 83.99,54.23 ; 126.62,19.46 J1.2 125.65,20.43 ; 92.73,4.65 J12.8 ; J12.8 92.73,6.89 ; J12.8 93.85,5.77 ; J12.8 91.61,5.77 ; J8.4 101.47,54.23 ; J8.4 100.35,53.11 ; J8.4 99.23,54.23 ; J8.4 100.35,55.35 ; 8.08,58.2 J15.4 ; J15.4 9.05,57.23 ; J15.4 10.02,58.2 ; J11.4 60.35,55.35 ; J11.4 59.23,54.23 ; J11.4 61.47,54.23 ; J11.4 60.35,53.11 ; 116.46,1.81 J7.3 115.45,2.83 ; J11.16 46.23,54.23 ; J11.16 45.11,53.11 ; J11.16 45.11,55.35 ; J11.16 43.99,54.23 ; 126.62,11.46 J1.10 125.65,10.5 ; 125.8,26.05 J3.1 ; J3.1 126.77,27.02 ; J3.1 124.83,27.02 ; 94.15,54.23 J8.8 ; J8.8 95.27,53.11 ; J8.8 95.27,55.35 ; J8.8 96.39,54.23 ; J12.16 102.89,6.89 ; J12.16 102.89,4.65 ; J12.16 104.01,5.77 ; J12.16 101.77,5.77 ; 10.08,58.2 J15.3 11.05,57.23 ; J13.4 47.65,6.89 ; J13.4 48.77,5.77 ; J13.4 47.65,4.65 ; J13.4 46.53,5.77
  BOTTOM w0.305: U34.10 v1(87.48,13.79) ; U32.19 61.74,10.06 v1(61.98,10.31) ; U32.10 v1(66.94,13.69) ; U33.19 89.77,10.13 v1(89.92,10.28) ; U34.19 82.28,10.13 v1(82.43,10.28) ; U31.10 v1(75.06,16.48) ; v1(70.11,7.72) 69.86,7.97 U31.19 ; U33.10 v1(94.97,13.69)
  BOTTOM w0.381: C58.2 v1(42.2,46.58) ; C283.2 86.59,47.64 v1(86.51,47.56) ; v1(47.92,38.07) 48.17,38.32 C43.2 ; C260.2 v1(84.91,27.66) ; C248.1 103.09,27.02 v1(103.13,27.06) ; v1(82.91,29.66) 83.41,30.16 C259.2 ; v1(114.85,15.21) 114.81,15.17 C247.1 ; C46.2 47.76,18.99 v1(47.92,19.15) ; v1(92.97,38.32) 92.84,38.2 C255.2 ; C7.2 35.15,52.99 ; C275.2 96.4,24.99 v1(95.89,25.5) ; C31.2 100.07,33.25 v1(99.32,33.25) ; v1(82.91,27.66) 83.41,27.16 C258.2 ; U5.52 v1(119.93,48.74) ; C252.1 105.7,31.05 v1(105.92,30.83) ; P1.J8 v1(84.91,29.66) ; v1(45.25,19.15) 45.1,18.99 C55.2 ; C10.2 33.37,52.99 ; v1(74.17,19.02) 74.93,19.78 C254.2 ; C277.2 81.43,31.15 v1(81.91,30.66) ; v1(45.25,36.67) 44.51,36.67 C51.2 ; C267.2 90,25.75 v1(89.91,25.66) ; C228.1 v1(38.09,23.97) ; C8.2 36.04,52.99 ; C271.2 79.89,34.68 v1(79.91,34.66) ; C229.1 v1(38.09,27.02) ; v1(115.64,46) 115.13,46.51 U5.46 ; v1(121.92,20.29) 121.54,20.67 121.54,22.19 121.8,22.45 U6.2 ; v1(46.65,21.81) 46.39,22.07 C54.2 ; C227.1 v1(38.09,20.92) ; C233.1 37.83,39.21 v1(38.09,38.96) ; C263.2 88.9,37.31 v1(89.03,37.43) ; C44.2 47.76,36.51 v1(47.92,36.67) ; C251.1 106.72,31.18 v1(107.07,30.83) ; v1(47.92,20.54) 48.17,20.8 C45.2 ; C245.1 115.89,27.15 v1(115.85,27.19) ; C35.2 v1(116.5,50.39) ; C253.1 v1(114.05,30.7) ; C285.2 71.73,47.51 v1(71.63,47.42) ; v1(85.91,25.66) 86.41,25.16 C257.2 ; U5.28 v1(100.73,46.01) ; v1(46.65,39.34) 46.65,39.97 C47.2 ; v1(45.25,21.81) 44.74,22.32 C56.2 ; C231.1 v1(38.09,33.12) ; C266.2 v1(81.03,40.23) ; C33.2 112.53,50.26 v1(112.02,49.75) ; C60.2 40.93,42.01 v1(41.31,42.39) ; C226.1 v1(38.09,17.88) ; C36.2 v1(113.03,27.66) ; C242.2 67.2,32.97 ; C270.2 75.31,30.68 v1(75.29,30.66) ; U5.41 111.13,48.61 v1(111,48.74) ; v1(89.91,22.66) 89.91,21.95 C268.2 ; C246.1 111.13,30.7 v1(111,30.83) ; v1(45.27,39.24) 44.66,39.85 C48.2 ; U5.6 v1(117.53,37.43) ; C284.2 v1(79,47.52) ; C232.1 v1(38.09,36.16) ; C9.2 34.26,52.99 ; U5.12 112.73,35.2 v1(113.24,34.69) ; v1(95.05,47.49) 95,47.44 C282.2 ; v1(76.91,35.66) 76.84,35.73 C262.2 ; v1(81.91,25.66) 81.41,25.16 C276.2 ; C230.1 v1(38.09,30.07) ; v1(79.91,22.66) 79.89,22.64 C264.2 ; C265.2 82.3,20.8 v1(82.94,20.16) ; C57.2 47.41,43.66 47.79,43.28 v1(47.79,42.9) ; C256.2 v1(84.91,30.66) ; C269.2 v1(74.81,24.61) ; C59.2 v1(41.31,40.1) ; U5.54 v1(121.53,48.74) ; C244.1 v1(100.21,16.1) ; C37.2 v1(108.59,16.23) ; C38.2 v1(83.06,19.02) ; R11.1 v1(123.32,26.13)
  vias: v1(8.72,55.37) v1(8.72,54.1) v1(9.66,48.36) v1(9.99,55.37) v1(9.99,54.1) v1(10.29,12.03) v1(10.29,10.76) v1(10.93,52.67) v1(10.93,51.02) v1(10.93,49.63) v1(10.93,48.36) v1(11.26,55.37) v1(11.26,54.1) v1(11.31,12.03) v1(11.31,10.76) v1(12.53,55.37) v1(12.65,54.1) v1(22.48,53.06) v1(23.75,53.06) v1(25.79,52.93) v1(25.79,51.79) v1(27.06,52.93) v1(28.33,52.93) v1(30.74,52.93) v1(38.61,53.18) v1(38.61,51.91) v1(39.88,53.18) v1(39.88,51.91) v1(45.25,38.07) v1(45.25,20.54) v1(46.65,38.07) v1(46.65,36.67) v1(46.65,20.54) v1(46.65,19.15) v1(47.92,39.34) v1(47.92,21.81) v1(55.15,42.64) v1(56.68,42.01) v1(57.69,42.64) v1(58.96,43.66) v1(60.36,43.66) v1(60.74,41.5) v1(60.74,40.23) v1(60.74,39.09) v1(62.01,41.5) v1(64.27,31.97) v1(64.27,28.67) v1(65.16,31.97) v1(65.28,28.67) v1(118.24,55.21) v1(118.24,54.07) v1(118.24,7.21) v1(118.24,5.68) v1(118.26,52.91) v1(119.53,52.91) v1(119.64,7.21) v1(120.91,7.21) v1(122.05,7.21) v1(122.18,53.31) v1(123.58,53.31) v1(123.58,7.21) v1(123.58,5.68)
